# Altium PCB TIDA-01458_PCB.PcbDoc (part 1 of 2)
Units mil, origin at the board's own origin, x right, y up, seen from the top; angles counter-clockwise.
Board outline 4724.41 x 3937.01 mil, 4 copper layers (Top Layer, GND, PWR, Bottom Layer), stack 62.2 mil thick; 188 components, 87 nets, 511 pads, 463 vias.
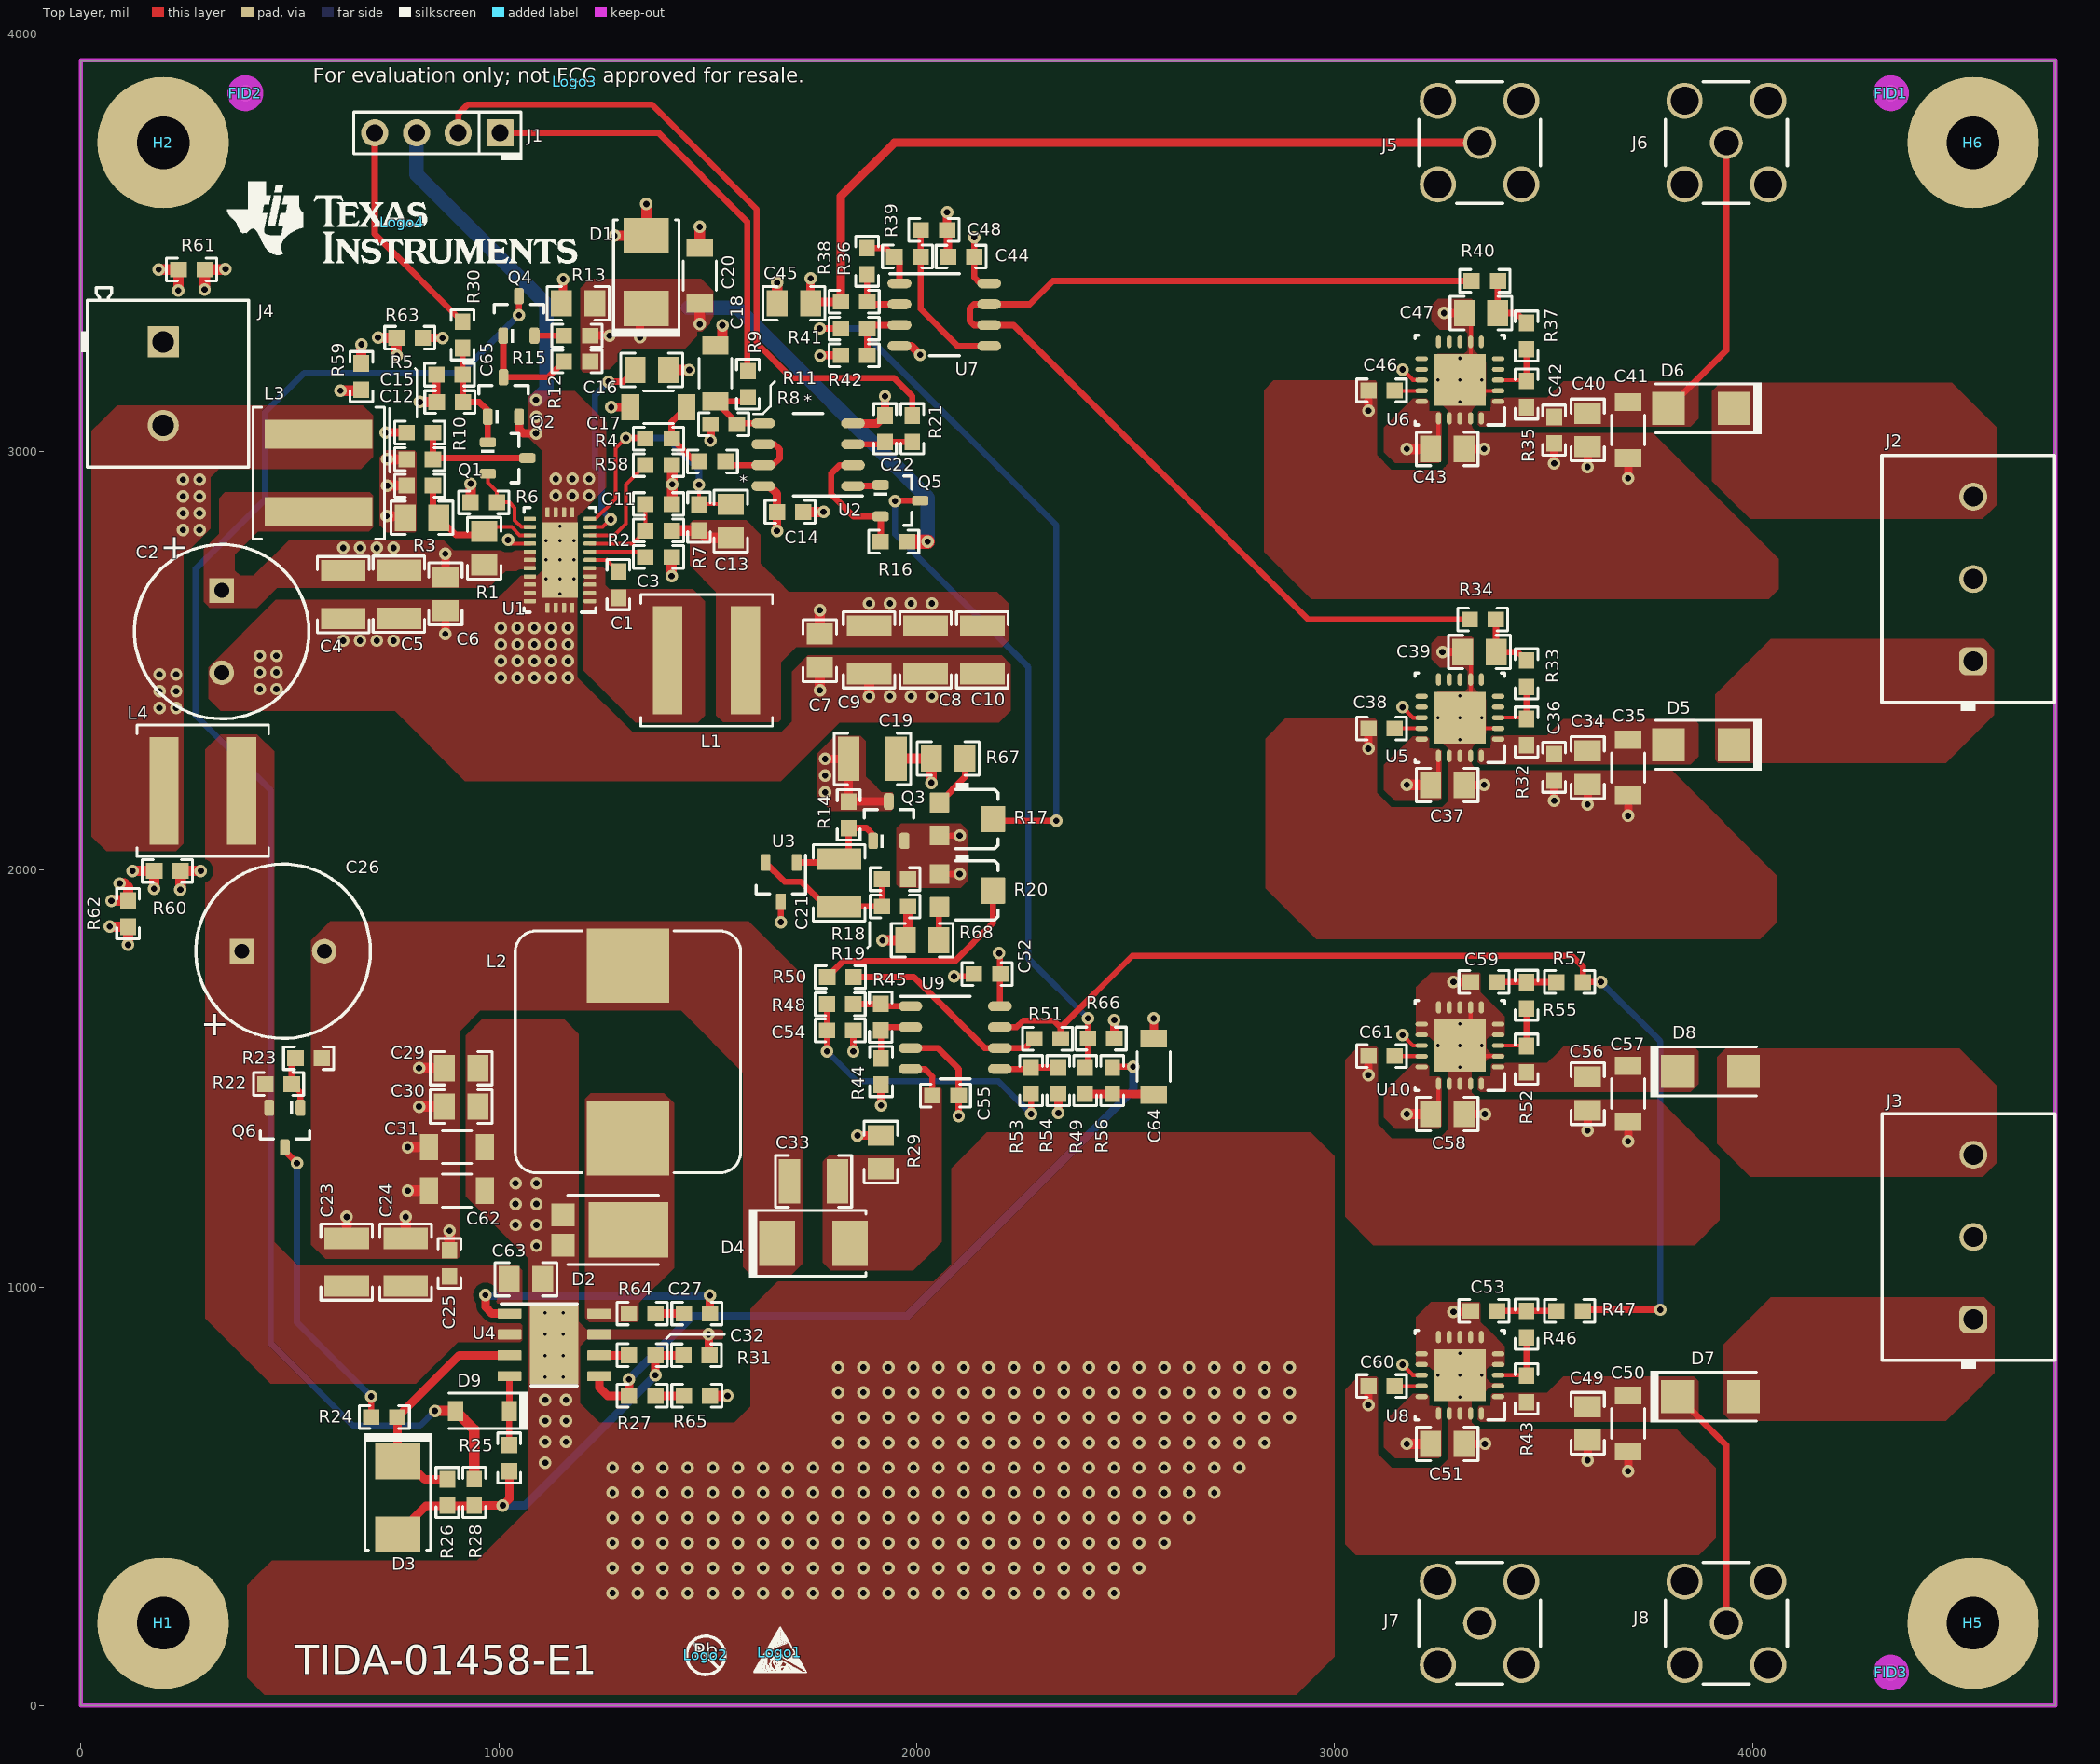
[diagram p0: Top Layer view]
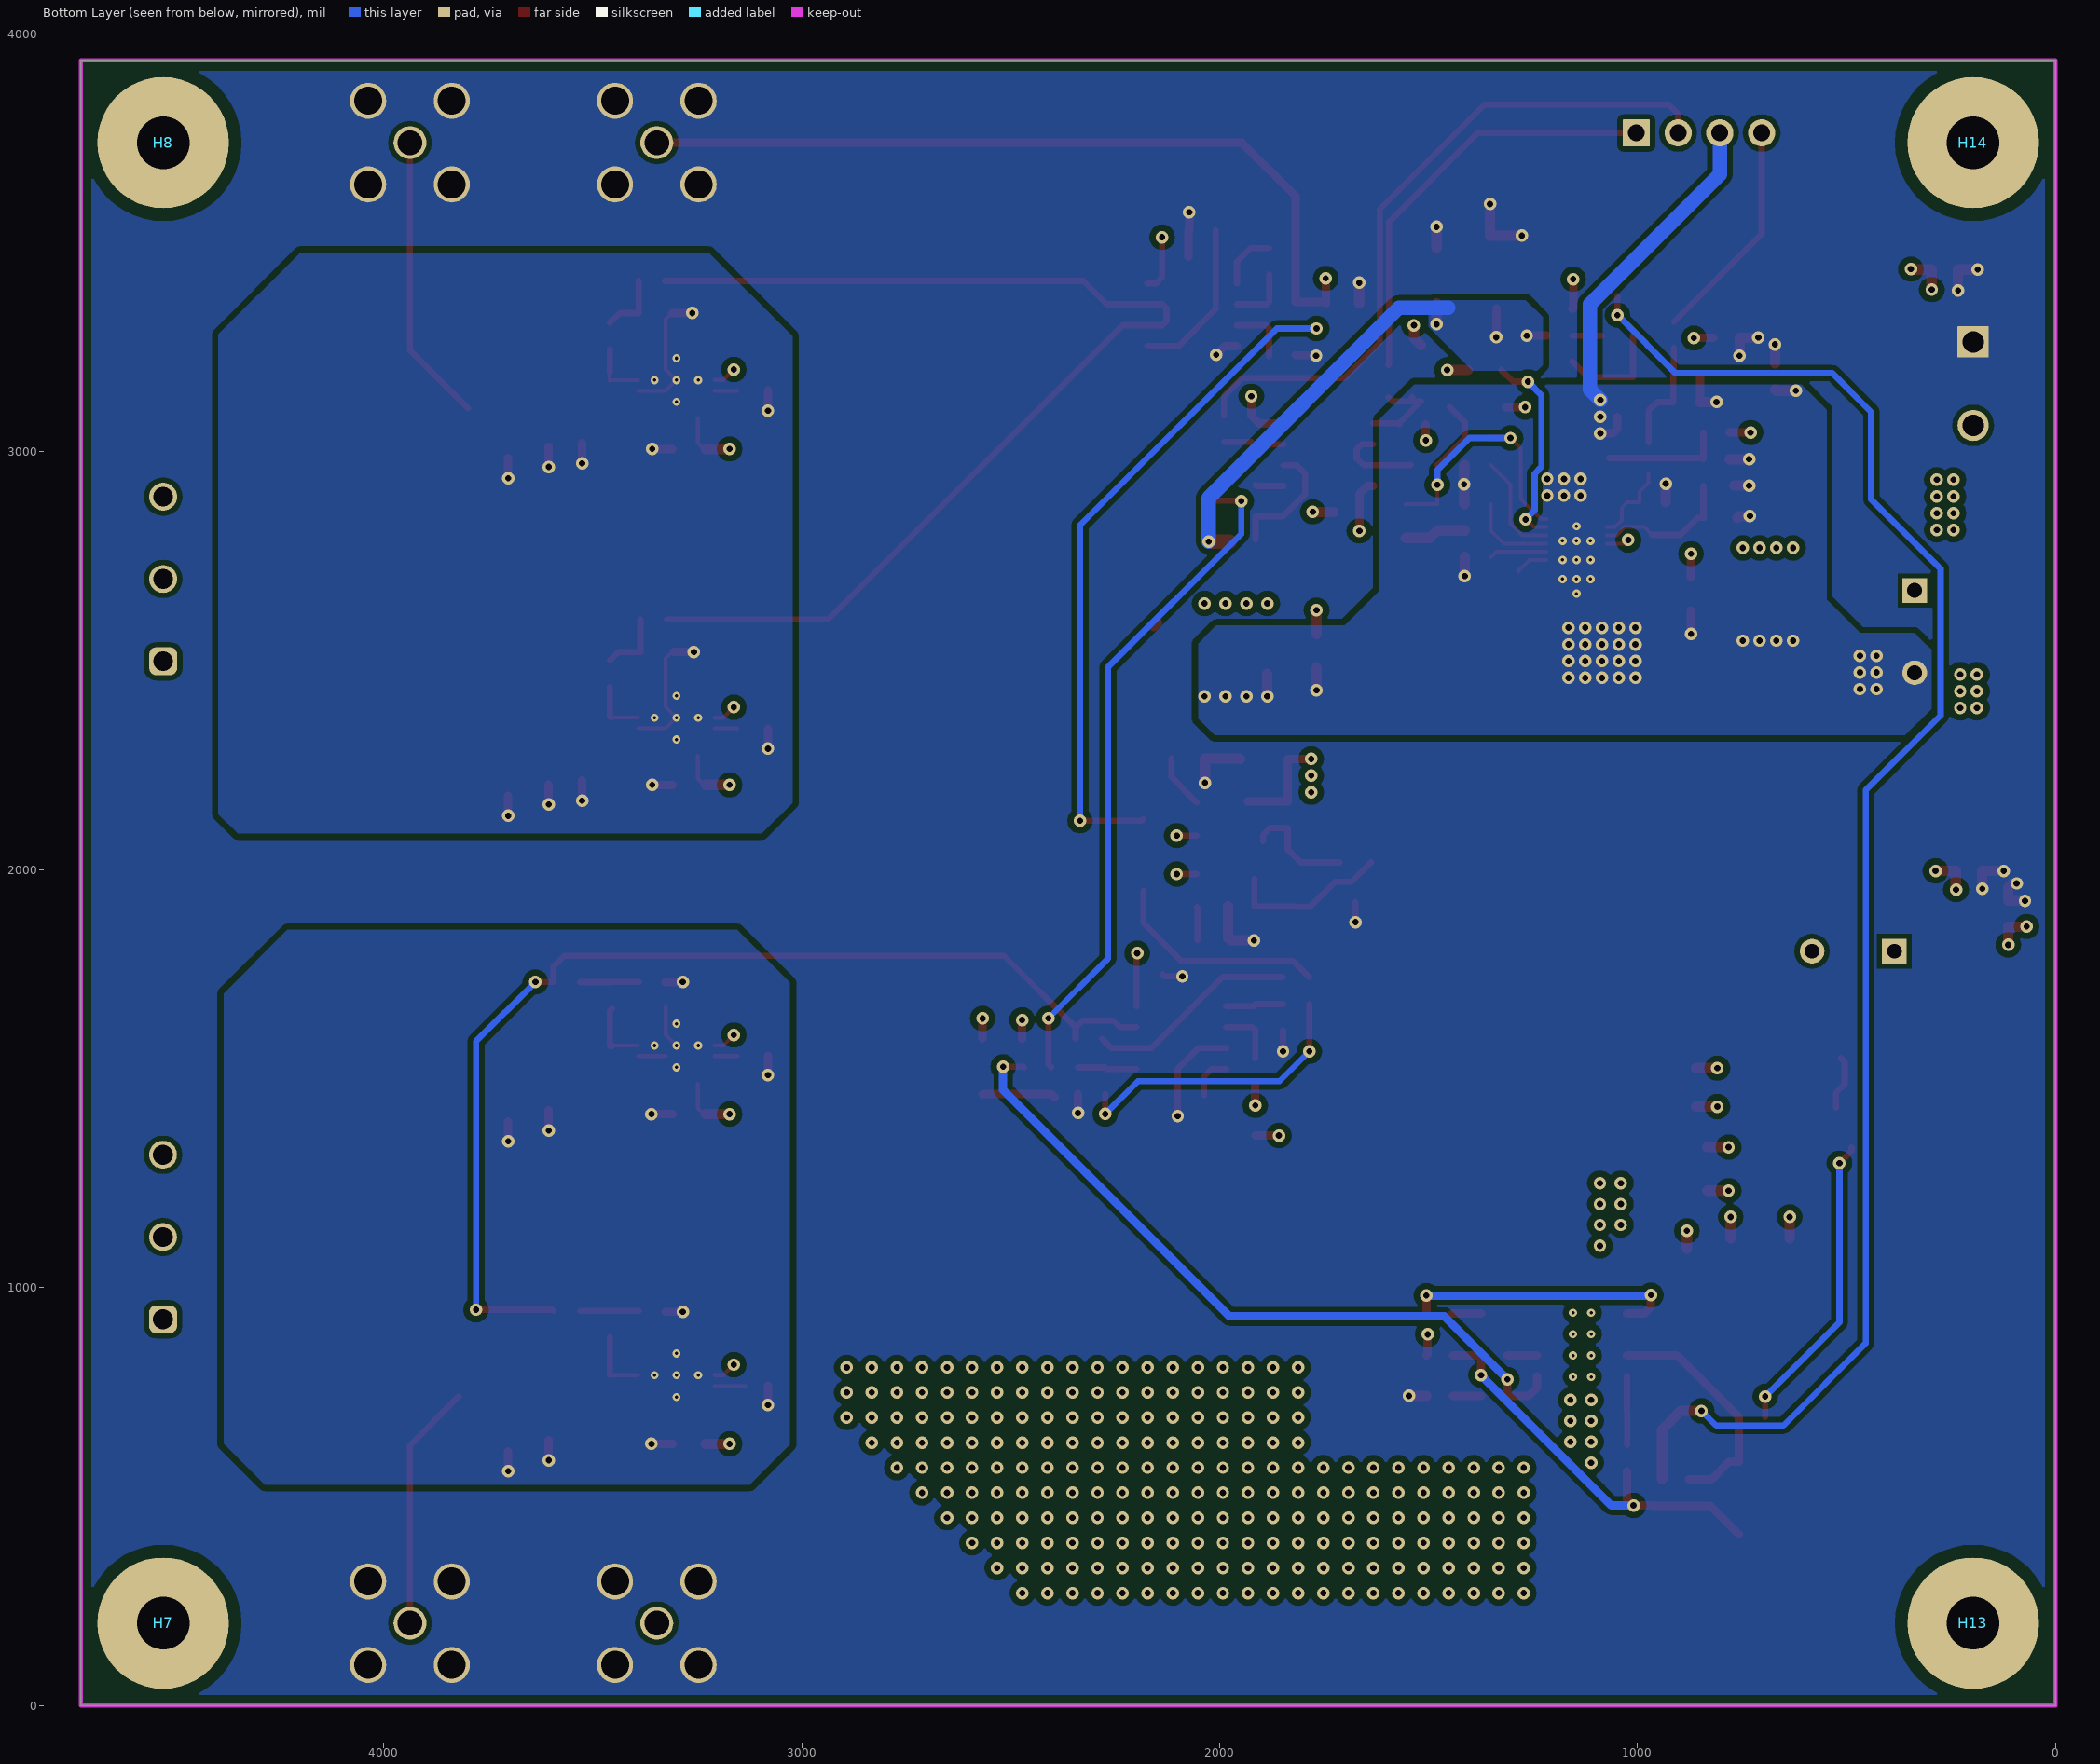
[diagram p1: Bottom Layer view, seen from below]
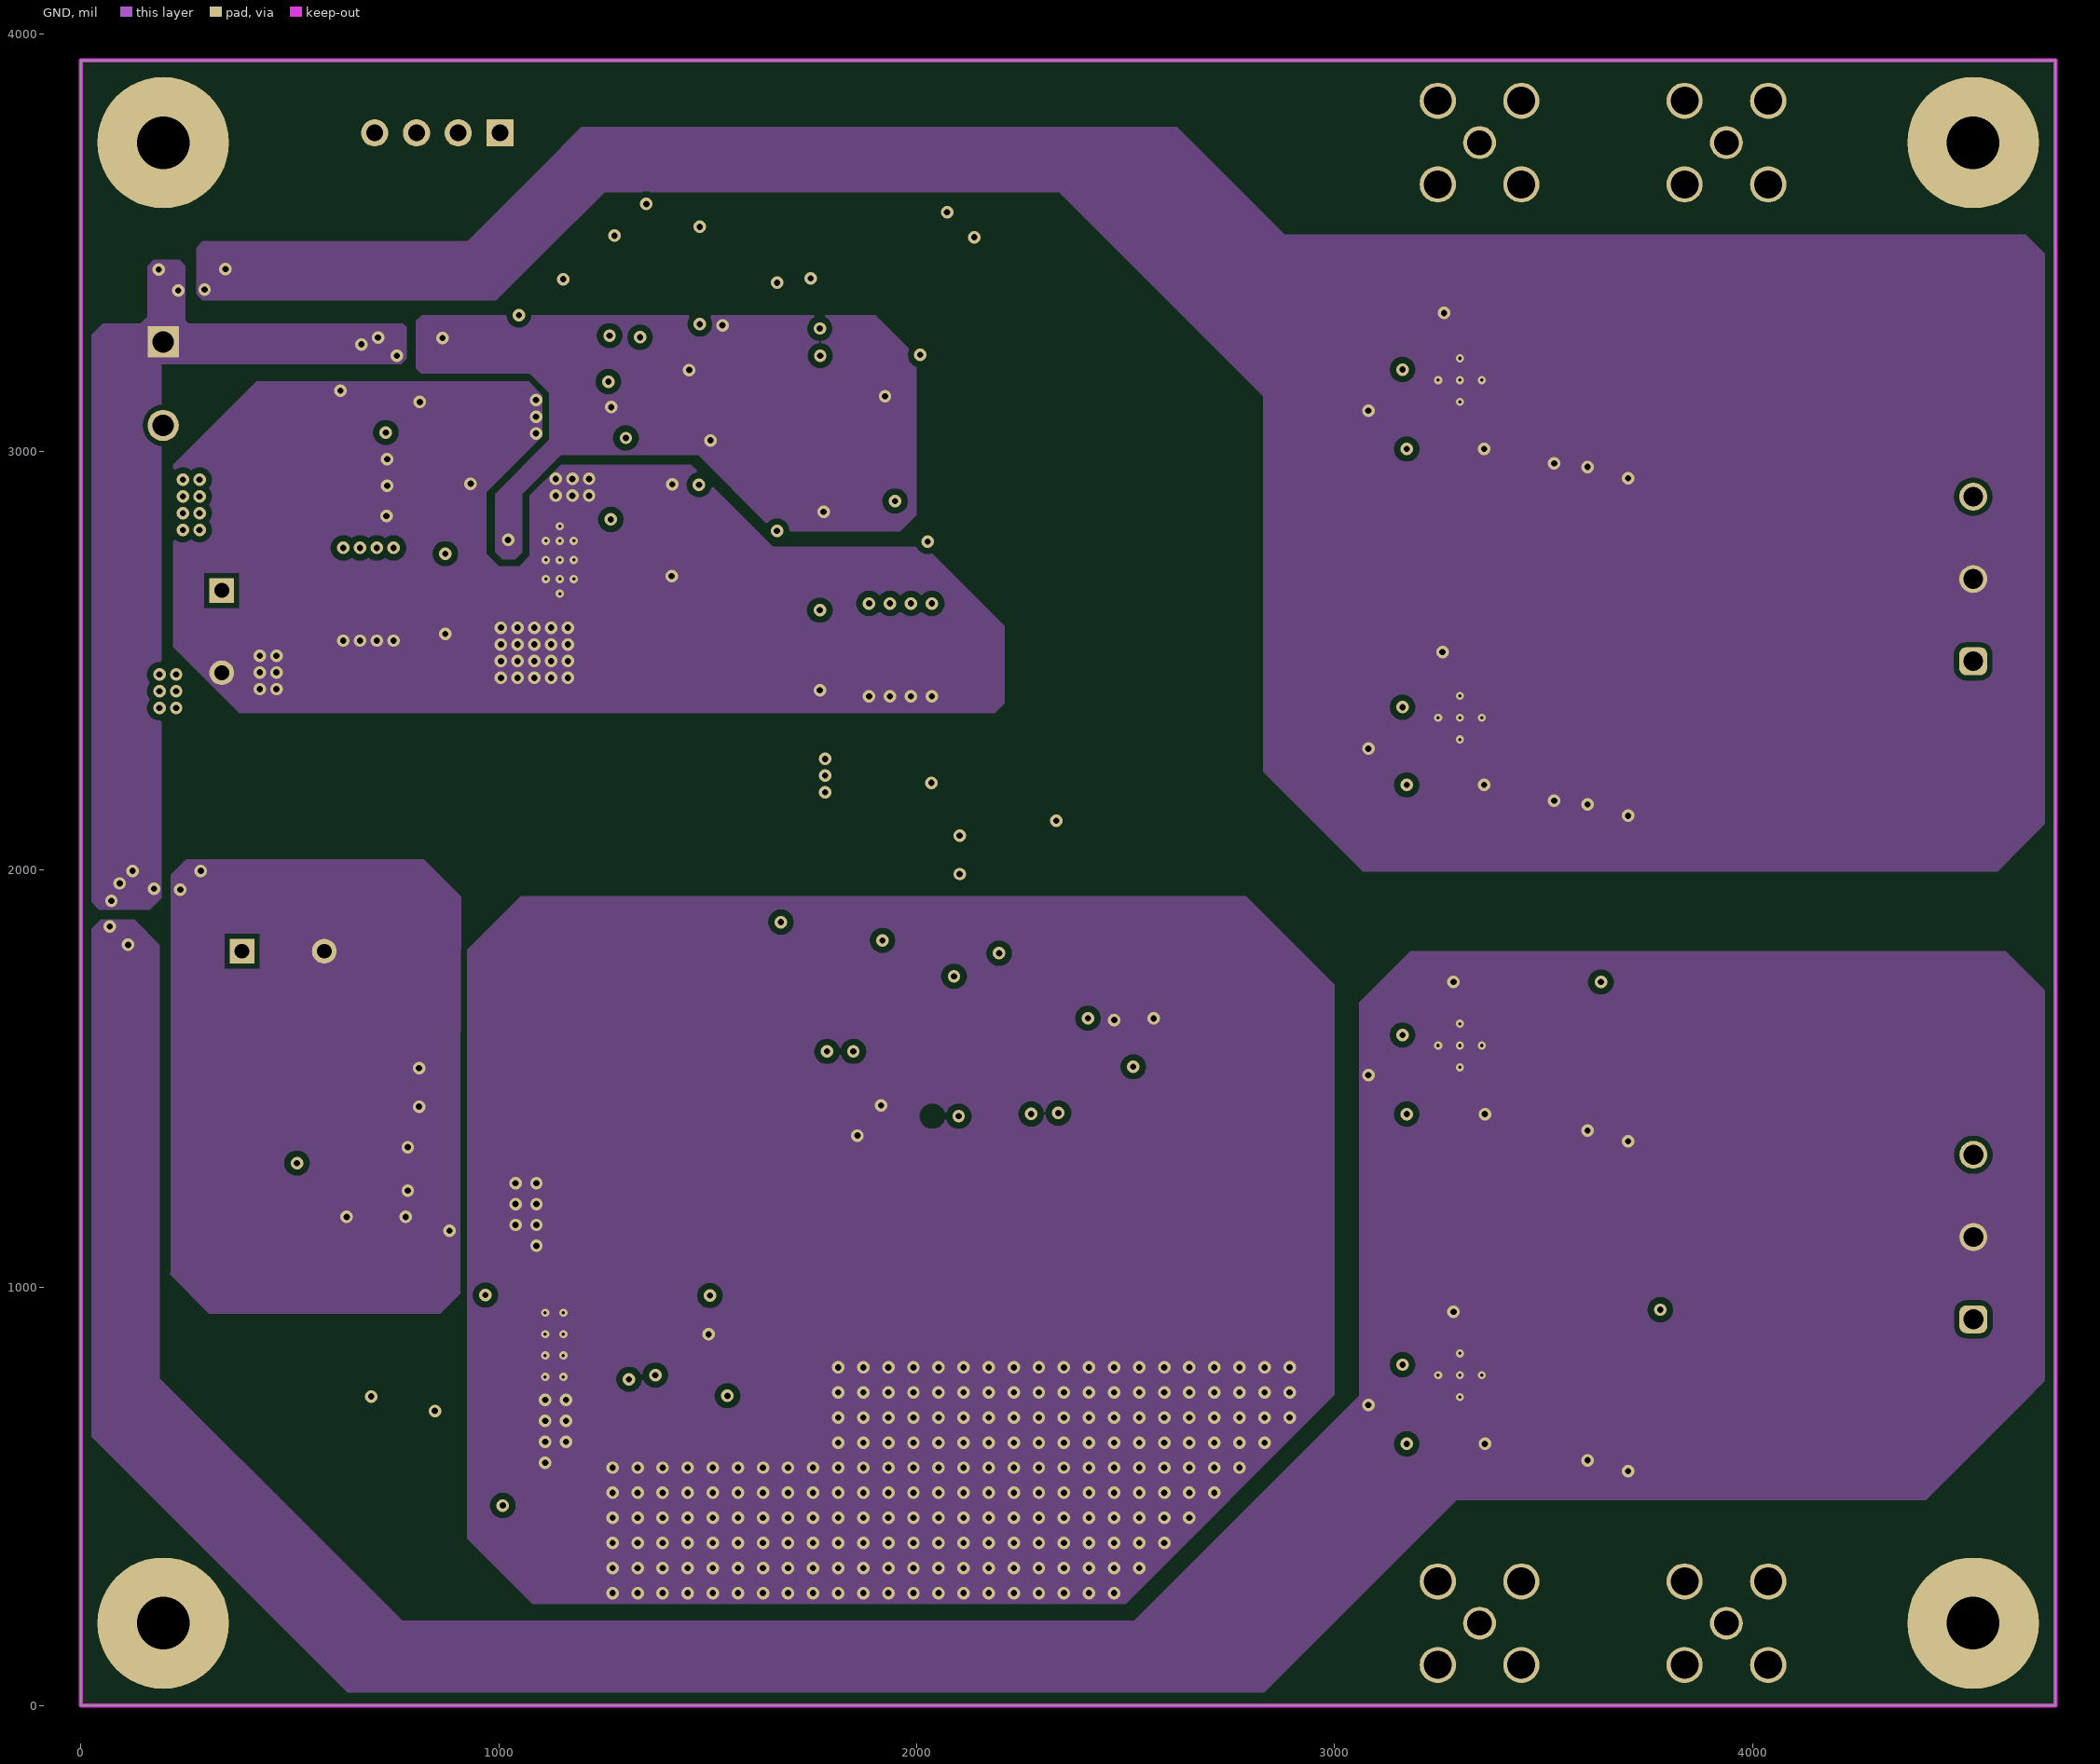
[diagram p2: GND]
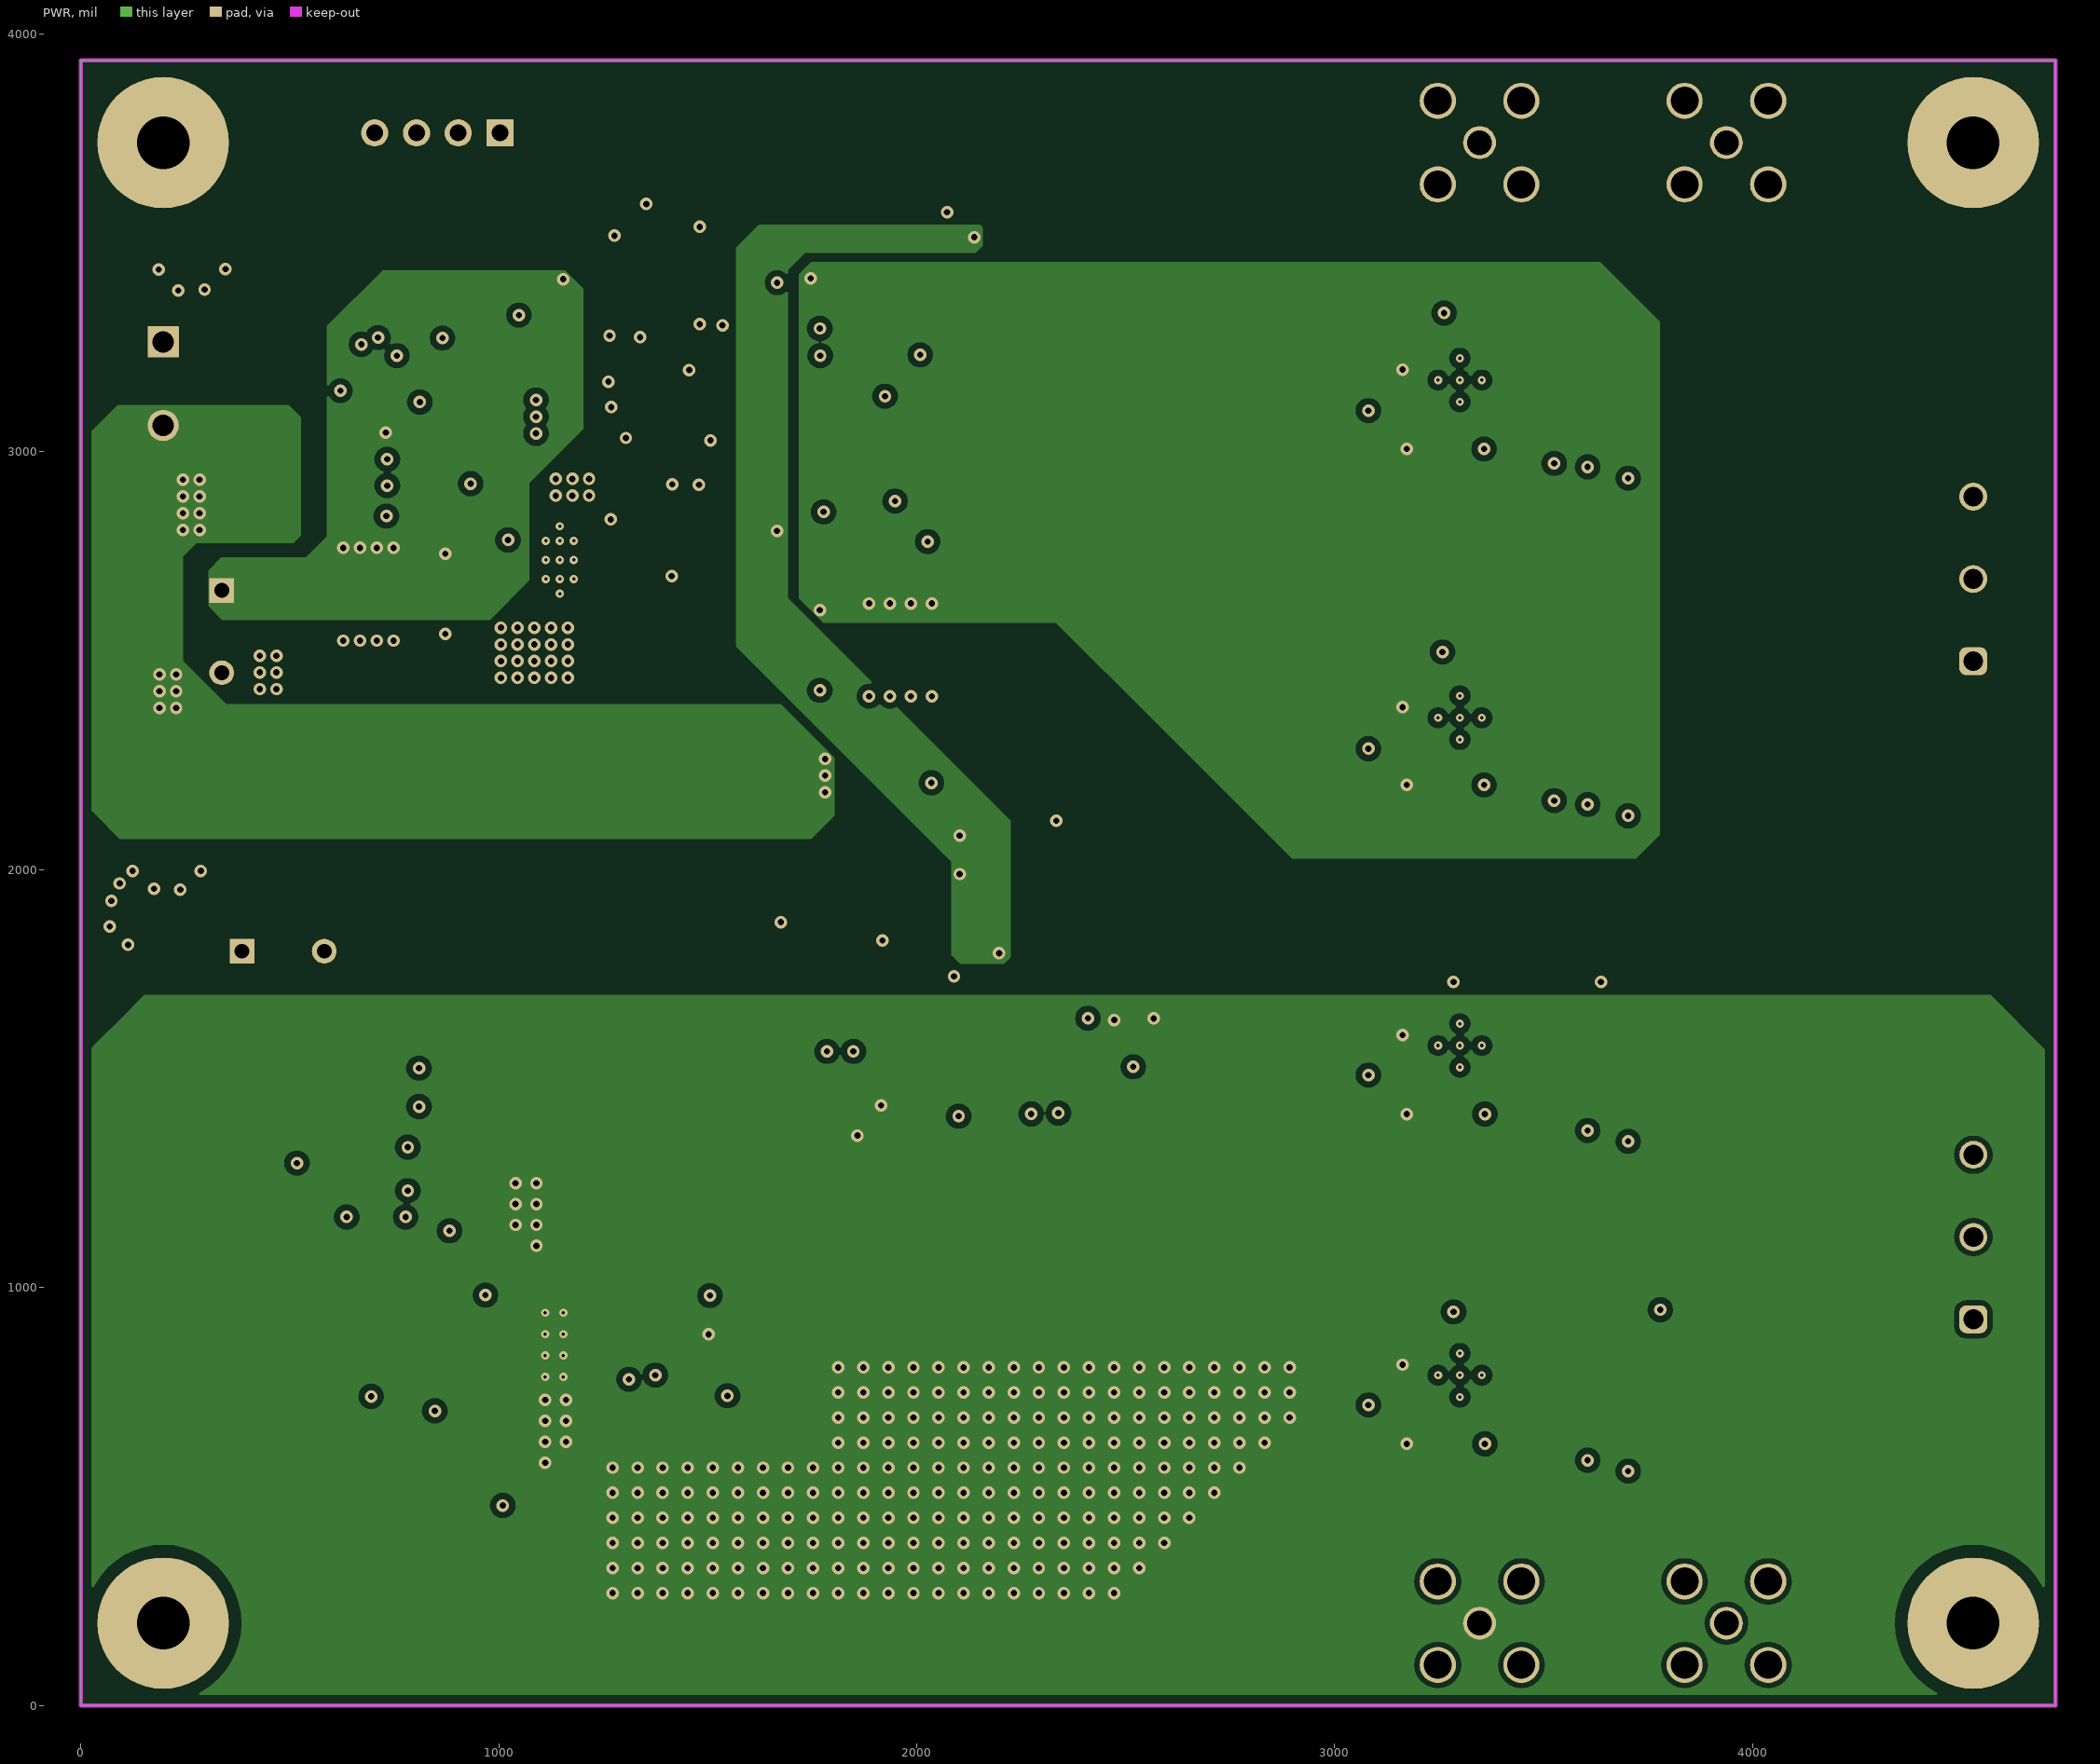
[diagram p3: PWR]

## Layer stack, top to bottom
Top Solder: solder mask 0.4, Solder Resist, Dk 3.5
Top Layer: signal copper 2.8
Dielectric1: core 8, FR-4 High Tg, Dk 4.8
GND: signal copper 2.8
Dielectric 2: prepreg 35, FR-4 High Tg, Dk 4.2
PWR: signal copper 2.8
Dielectric 3: core 8, FR-4 High Tg, Dk 4.2
Bottom Layer: signal copper 2.8
Bottom Solder: solder mask 0.4, Solder Resist, Dk 3.5

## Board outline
0,0 4724.41,0 4724.41,3937.01 0,3937.01

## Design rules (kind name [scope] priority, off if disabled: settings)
AcuteAngle [All] p1: minimum=4.50000000000000E+0001 checktracksonly=FALSE
AssemblyTestPointUsage [All] p1: valid=2
Clearance Clearance_MTG [InPadClass('MTG')] p1: gap=30
Clearance Clearance_Keepouts [IsKeepOut] p2: gap=20
Clearance Clearance_Poly [InPolygon] p3: gap=15 except(12: Track-Poly SMDPad-Poly THPad-Poly)
Clearance [All] p4: gap=7.7
ComponentClearance ComponentClearance_MountingHoles_FiducialMarks [InComponentClass('Mounting Holes') vs InComponentClass('FiducialMark')] p1: gap=10 collisioncheckmode=3 verticalgap=10 showdistances=FALSE
ComponentClearance ComponentClearance_Shunt [InComponentClass('Header') vs InComponentClass('Shunt')] p2: gap=0 collisioncheckmode=3 verticalgap=0 showdistances=FALSE
ComponentClearance ComponentClearance_Logo [InComponentClass('Logo')] p3: gap=20 collisioncheckmode=3 verticalgap=10 showdistances=FALSE
ComponentClearance ComponentClearance_ScrewToNut [(HasFootprint('NY PMS 440 0025 PH')) vs (HasFootprint('Keystone_1902C'))] p4: gap=5 collisioncheckmode=3 verticalgap=10 showdistances=FALSE
ComponentClearance ComponentClearance_MountingHoles [InComponentClass('Mounting Holes')] p5: gap=50 collisioncheckmode=3 verticalgap=100000 showdistances=FALSE
ComponentClearance ComponentClearance_SmallPassives [HasFootprint('0201*') or HasFootprint('0402*') or HasFootprint('0508') or HasFootprint('0603*') or HasFootprint('0612') or HasFootprint('0805*') or HasFootprint('0815*') or HasFootprint('0830*') or HasFootprint('1206*') or HasFootprint('1210*') or HasFootprint('1808*') or HasFootprint('1812*') or HasFootprint('1825*') or HasFootprint('2010*') or HasFootprint('2220*') or HasFootprint('2225*') or HasFootprint('2512*') or HasFootprint('2728*') or HasFootprint('3518*') vs HasFootprint('0201*') or HasFootprint('0402*') or HasFootprint('0508') or HasFootprint('0603*') or HasFootprint('0612') or HasFootprint('0805*') or HasFootprint('0815*') or HasFootprint('0830*') or HasFootprint('1206*') or HasFootprint('1210*') or HasFootprint('1808*') or HasFootprint('1812*') or HasFootprint('1825*') or HasFootprint('2010*') or HasFootprint('2220*') or HasFootprint('2225*') or HasFootprint('2512*') or HasFootprint('2728*') or HasFootprint('3518*')] p6: gap=14.96 collisioncheckmode=3 verticalgap=10 showdistances=FALSE
ComponentClearance ComponentClearance_THtoSMT [IsThruComponent vs IsSMTComponent] p7: gap=5 collisioncheckmode=3 verticalgap=30 showdistances=FALSE
ComponentClearance ComponentClearance_THtoTH [IsThruComponent vs IsThruComponent] p8: gap=10 collisioncheckmode=3 verticalgap=10 showdistances=FALSE
ComponentClearance [All] p9: gap=10 collisioncheckmode=3 verticalgap=10 showdistances=FALSE
DiffPairsRouting [All] p1: maxlimit=100 minlimit=10 mostfreqgap=10 toplayer_minwidth=15 toplayer_maxwidth=15 toplayer_prefwidth=15 midlayer1_minwidth=15 midlayer1_maxwidth=15 midlayer1_prefwidth=15 midlayer2_minwidth=15 midlayer2_maxwidth=15 midlayer2_prefwidth=15 bottomlayer_minwidth=15 bottomlayer_maxwidth=15 bottomlayer_prefwidth=15 maxuncoupledlength=1000
FabricationTestPointUsage TestPointUsage [All] p1: valid=2 allowmultiple=FALSE
FabricationTestpoint Testpoint [All] p1: side=3 testpointundercomponent=TRUE minsize=40 maxsize=100 preferedsize=60 minholesize=0 maxholesize=40 preferedholesize=32 testpointgrid=1 allowsidetop=TRUE allowsidebottom=TRUE usegrid=TRUE gridtolerance=0.01
FanoutControl Fanout_LCC [IsLCC] p1: bgadir=Out bgaviamode=Centered fanoutstyle=Auto fanoutdirection=Alternating viagrid=1 // Fanout_LCC (Default Rule)
FanoutControl Fanout_BGA [IsBGA] p2: bgadir=Out bgaviamode=Centered fanoutstyle=Auto fanoutdirection=Alternating viagrid=1 // Fanout_BGA (Default Rule)
FanoutControl Fanout_Default [All] p4: bgadir=Out bgaviamode=Centered fanoutstyle=Auto fanoutdirection=Alternating viagrid=1 // Fanout_Default (Default Rule)
FanoutControl Fanout_Small [(CompPinCount < 5)] p5: bgadir=Out bgaviamode=Centered fanoutstyle=Auto fanoutdirection=OutThenIn viagrid=1 // Fanout_Small (Default Rule)
Height [All] p1: minheight=0 maxheight=1100 prefheight=500
HoleSize [All] p1: absolutevalues=TRUE maxlimit=251 minlimit=7.87 maxpercent=80.000 minpercent=20.000
MinimumAnnularRing MinimumAnnularRing_ThermalPadVias [IsVia and InAnyComponent] p1: minimumring=5.91
MinimumAnnularRing [All] p2: minimumring=6
MinimumSolderMaskSliver MinimumSolderMaskSliver_Logo [InComponentClass('Logo') vs InComponentClass('Logo')] p1: minsoldermaskwidth=0.7
MinimumSolderMaskSliver [All] p2: minsoldermaskwidth=3.94
PlaneConnect [All] p1: planeconnectstyle=Relief reliefexpansion=10 reliefentries=4 reliefconductorwidth=10 reliefairgap=10
PolygonConnect [All] p1: connectstyle=Direct reliefconductorwidth=10 reliefentries=4 polygonreliefangle="90 Angle" airgapwidth=10
RoutingVias [All] p1: holewidth=12 width=24 viastyle="Through Hole" minholewidth=7.87 minwidth=19.68 maxholewidth=40 maxwidth=65
RoutingVias ThermalPadVias [IsVia and InAnyComponent] p2: holewidth=7.87 width=19.68 viastyle="Through Hole" minholewidth=7.87 minwidth=19.68 maxholewidth=12.99 maxwidth=23.62
SilkToBoardRegionClearance [Not ((IsComment or IsDesignator) And (Hide <> 'False')) and not InRegion(1000,500,4000,800)] p1:
SilkToSilkClearance SilkToSilkClearance_Pb-FreeLogo [(HasFootprint('Pb-Free_Overlay_Medium') OR HasFootprint('Pb-Free_Overlay_Small')) vs (HasFootprint('Pb-Free_Overlay_Medium') OR HasFootprint('Pb-Free_Overlay_Small'))] p1: silktosilkclearance=0
SilkToSilkClearance [All] p2: silktosilkclearance=4
SilkToSolderMaskClearance SilkToComponentPadClearance [IsPad and InAnycomponent] p1: minsilkscreentomaskgap=5 clearancetoexposedcopper=TRUE
SilkToSolderMaskClearance "Silk to Solder Mask Opening" [All] p2: minsilkscreentomaskgap=4 clearancetoexposedcopper=FALSE
SolderMaskExpansion [All] p1: expansion=2.5
Width [All] p1: maxlimit=100 minlimit=6 preferedwidth=10 checkconnectedcopper=TRUE
14 further rules are at their usual default settings.

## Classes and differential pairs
pad class MTG: H1-1 H2-1 H5-1 H6-1
component class AssemblyNote: ZZ1 ZZ2 ZZ3 ZZ4
component class FiducialMark: FID1 FID2 FID3
component class TIDA-01458_Hardware: FID1 FID2 FID3 H1 H2 H5 H6 H7 H8 H13 H14 Logo1 Logo2 Logo3 Logo4 ZZ1 ZZ2 ZZ3 ZZ4
component class "Mounting Holes": H1 H2 H5 H6
component class Header: J1
component class TIDA-01458-Sheet1: C1 C2 C3 C4 C5 C6 C7 C8 C9 C10 C11 C12 C13 C14 C15 C16 C17 C18 C19 C20 C21 C22 C23 C24 C25 C26 C27 C29 C30 C31 C32 C33 C62 C63 C64 C65 D1 D2 D3 D4 D9 J1 J4 L1 L2 L3 L4 Q1 Q2 Q3 Q4 Q5 Q6 R1 R2 R3 R4 R5 R6 R7 R8 R9 R10 R11 R12 R13 R14 R15 R16 R17 R18 R19 R20 R21 R22 R23 R24 R25 R26 R27 R28 R29 R30 R31 R49 R56 R58 R64 R65 R66 R67 R68 U1 U2 U3 U4
component class TIDA-01458_Sheet2: C34 C35 C36 c37 c38 C39 C40 C41 C42 C43 C44 C45 C46 C47 C48 C49 C50 C51 C52 C53 C54 C55 C56 C57 C58 C59 C60 C61 D5 D6 D7 D8 J2 J3 J5 J6 J7 J8 R32 R33 R34 R35 R36 R37 R38 R39 R40 R41 R42 R43 R44 R45 R46 R47 R48 R50 R51 R52 R53 R54 R55 R57 R59 R60 R61 R62 R63 U5 U6 U7 U8 U9 U10
component class Logo: Logo4

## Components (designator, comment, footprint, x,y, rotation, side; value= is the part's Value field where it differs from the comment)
C1 "GRM188R61E474KA12D" 0603 1286,2682.25 r90 top
C2 "35ZL470MEFC10X20" ZL_1000x2000 337,2569.83 r270 top
C3 "C1608X5R1V225K080AC" 0603 1382,2748.25 r180 top
C4 "GRM32ER71H106KA12L" 1210_270 628,2658.25 r90 top
C5 "GRM32ER71H106KA12L" 1210_270 761,2659.25 r90 top
C6 "GRM21BR71H474KA88L" 0805_HV 872,2660.25 r90 top
C7 "GRM21BR71H474KA88L" 0805_HV 1768,2524.25 r90 top
C8 "GRM32ER71E226KE15L" 1210_270 2021,2526.25 r270 top
C9 "GRM32ER71E226KE15L" 1210_270 1886,2526.25 r270 top
C10 "GRM32ER71E226KE15L" 1210_270 2157,2526.25 r270 top
C11 "C1608X5R1H105K080AB" 0603 1382,2875.05 r180 top
C12 "C1608X7R1H104K080AA" 0603 811,2919.25 r180 top
C13 "08055A4R7CAT2A" 0805_HV 1555,2834.25 r270 top
C14 "C1608X7R1H104K080AA" 0603 1697,2856.25 r0 top
C15 "C1608X7R1H104K080AA" 0603 811,2982.25 r180 top
C16 "08055C223KAT2A" 0805_HV 1366,3196 r180 top
C17 "C3216X5R1H106K160AB" 1206_180 1382,3107 r180 top
C18 "C3216X5R1H106K160AB" 1206_180 1518,3188 r90 top
C19 "GRM32ER71H106KA12L" 1210_270 1894,2265.25 r0 top
C20 "C3216X5R1H106K160AB" 1206_180 1481,3422 r90 top
C21 "GRM32ER71H106KA12L" 1210_270 1814,1968.25 r270 top
C22 "C1608X7R1H104K080AA" 0603 1924,3055.25 r90 top
C23 "GRM32ER71H475KA88L" 1210_270 636,1061 r90 top
C24 "GRM32ER71H475KA88L" 1210_270 777,1061 r90 top
C25 "C1608X7R1H104K080AA" 0603 882,1058 r90 top
C26 "35ZL470MEFC10X20" ZL_1000x2000 484,1805 r0 top
C27 "C1608X7R1H104K080AA" 0603 1474,938 r0 top
C29 "GRM21BR71E105KA99L" 0805_HV 910,1525 r0 top
C30 "GRM21BR71E105KA99L" 0805_HV 910,1433 r0 top
C31 "C3216X5R1E476M160AC" 1206_190 900,1336 r0 top
C32 "GRM188R71E273KA01D" 0603 1343,838 r0 top
C33 "GRM32ER71E226KE15L" 1210_270 1753,1254 r180 top
C34 "C2012X5R1V106K085AC" 0805_HV 3605,2244.25 r90 top
C35 "C3216X5R1E476M160AC" 1206_190 3702,2244.25 r270 top
C36 "C1608X7R1H104K080AA" 0603 3525,2245.25 r270 top
C37 "C2012X5R1V106K085AC" 0805_HV 3269,2203 r180 top
C38 "C1608X5R1H105K080AB" 0603 3112,2338 r0 top
C39 "C2012X5R1V106K085AC" 0805_HV 3346,2521 r0 top
C40 "C2012X5R1V106K085AC" 0805_HV 3605,3052.25 r90 top
C41 "C3216X5R1E476M160AC" 1206_190 3702,3052.25 r270 top
C42 "C1608X7R1H104K080AA" 0603 3525,3052 r270 top
C43 "C2012X5R1V106K085AC" 0805_HV 3269,3007 r180 top
C44 "C1608X7R1H104K080AA" 0603 2106,3467.25 r180 top
C45 "C2012X5R1V106K085AC" 0805_HV 1705.85,3355.3 r0 top
C46 "C1608X5R1H105K080AB" 0603 3112,3147 r0 top
C47 "C2012X5R1V106K085AC" 0805_HV 3350,3332.25 r0 top
C48 "C1608X5R1H105K080AB" 0603 2041,3531.25 r180 top
C49 "C2012X5R1V106K085AC" 0805_HV 3605,675 r90 top
C50 "C3216X5R1E476M160AC" 1206_190 3702,675 r270 top
C51 "C2012X5R1V106K085AC" 0805_HV 3269,626 r180 top
C52 "C1608X7R1H104K080AA" 0603 2168.17,1750.23 r180 top
C53 "C1608X5R1H105K080AB" 0603 3357,944 r0 top
C54 "C1608X7R1H104K080AA" 0603 1816.72,1615.25 r180 top
C55 "C1608X7R1H104K080AA" 0603 2068.72,1459.25 r0 top
C56 "C2012X5R1V106K085AC" 0805_HV 3605,1464.25 r90 top
C57 "C3216X5R1E476M160AC" 1206_190 3702,1464.25 r270 top
C58 "C2012X5R1V106K085AC" 0805_HV 3269,1415.25 r180 top
C59 "C1608X5R1H105K080AB" 0603 3357,1731.25 r0 top
C60 "C1608X5R1H105K080AB" 0603 3112,764.25 r0 top
C61 "C1608X5R1H105K080AB" 0603 3112,1554.25 r0 top
C62 "C3216X5R1E476M160AC" 1206_190 900,1232 r0 top
C63 "GRM21BR71E105KA99L" 0805_HV 1065,1020 r0 top
C64 "C3216X5R1H106K160AB" 1206_180 2567,1529 r90 top
C65 "06035A220JAT2A" 0603 882,3185 r180 top
D1 "1SMB5913BT3G" SMB 1353,3430.25 r90 top
D2 "PDS760-13" PowerDI5 1232,1138 r0 top
D3 "1SMB5913BT3G" SMB 758,497 r270 top
D4 "1SMB5913BT3G" SMB 1753,1106 r0 top
D5 "B260A-13-F" SMA 3877.05,2299.25 r180 top
D6 "B260A-13-F" SMA 3877.05,3104.25 r180 top
D7 "B260A-13-F" SMA 3899,739.25 r0 top
D8 "B260A-13-F" SMA 3899,1517.25 r0 top
D9 "1N4148W-TP" SOD-123 961,705 r180 top
FID1 "Fiducial" Fiducial10-20 4330.71,3858.27 r90 top
FID2 "Fiducial" Fiducial10-20 393.7,3858.27 r0 top
FID3 "Fiducial" Fiducial10-20 4330.71,78.74 r90 top
H1 "NY PMS 440 0025 PH" "NY PMS 440 0025 PH" 196.85,196.85 r0 top
H2 "NY PMS 440 0025 PH" "NY PMS 440 0025 PH" 196.85,3740.16 r0 top
H5 "NY PMS 440 0025 PH" "NY PMS 440 0025 PH" 4527.56,196.85 r0 top
H6 "NY PMS 440 0025 PH" "NY PMS 440 0025 PH" 4527.56,3740.16 r0 top
H7 "1902C" Keystone_1902C 4527.56,196.85 r180 bottom locked
H8 "1902C" Keystone_1902C 4527.56,3740.16 r180 bottom
H13 "1902C" Keystone_1902C 196.85,196.85 r180 bottom locked
H14 "1902C" Keystone_1902C 196.85,3740.16 r180 bottom
J1 "TSW-104-07-G-S" TSW-104-07-G-S 853,3763.25 r180 top
J2 "1792876" Phoenix_1792876 4527.56,2695.85 r90 top
J3 "1792876" Phoenix_1792876 4528,1121 r90 top
J4 "1715721" PhoenixContact_1715721 197,3163.25 r270 top
J5 "901-144-8RFX" Amphenol_901-144-8RFX 3346.46,3740.16 r0 top
J6 "901-144-8RFX" Amphenol_901-144-8RFX 3937.01,3740.16 r0 top
J7 "901-144-8RFX" Amphenol_901-144-8RFX 3346.46,196.85 r0 top
J8 "901-144-8RFX" Amphenol_901-144-8RFX 3937.01,196.85 r0 top
L1 "XAL7030-103MEB" XAL7030 1497,2501.25 r0 top
L2 "7443551331" WE-HCA1 1309,1564 r90 top locked
L3 "XAL7030-222MEB" XAL7030 569,2949.25 r270 top
L4 "XAL7030-222MEB" XAL7030 292,2189 r0 top
Logo1 "ESD Susceptible" ESD_Overlay_Small 1672,127 r0 top
Logo2 "Pb-Free Symbol" Pb-Free_Overlay_Small 1495,120 r0 top
Logo3 "FCC disclaimer" FCC_disclaimer 1182,3885.25 r0 top
Logo4 "Texas Instruments" TI_Stacked_Overlay_Small 769,3549.25 r0 top
Q1 "BC847CLT1G" SOT-23 1021,2985.25 r0 top
Q2 "BSS123" SOT-23 1011,3131.25 r90 top
Q3 "BC847CLT1G" SOT-23 1933,2116.25 r90 top
Q4 "BC857C-7-F" SOT-23 1048,3325.25 r90 top
Q5 "BC857C-7-F" SOT-23 1961,2883.25 r0 top
Q6 "BC857C-7-F" SOT-23 488,1383 r270 top
R1 "CRCW0805240KJNEA" 0805_HV 965,2769.25 r270 top
R2 "CRCW06030000Z0EA" 0603 1382,2811.65 r180 top
R3 "CRCW080547K0JNEA" 0805_HV 816,2842.25 r0 top
R4 "CRCW060368K0JNEA" 0603 1382,3031.85 r180 top
R5 "CRCW0603470RJNEA" 0603 811,3046.25 r180 top
R6 "CRCW0603100RFKEA" 0603 964,2879.25 r0 top
R7 "CRCW06031M00FKEA" 0603 1479,2843.25 r90 top
R8 "RC0603FR-074K7L" 0603 1511,2977.25 r180 top
R9 "CRCW060320K0JNEA" 0603 1596,3162 r270 top
R10 "RC0603FR-074K7L" 0603 883,3119.25 r0 top
R11 "CRCW060310K0FKEA" 0603 1538,3066 r0 top
R12 "CRCW06031K00FKEA" 0603 1187,3216.25 r180 top
R13 "CRCW08052K00JNEA" 0805_HV 1190,3355.25 r180 top
R14 "RC0603FR-074K7L" 0603 1837,2131.25 r90 top
R15 "CRCW06033K30JNEA" 0603 1187,3278.25 r0 top
R16 "CRCW06033K30JNEA" 0603 1945,2785.25 r0 top
R17 "TC33X-2-103E" Bourns_TC33X-2 2125,2121.25 r0 top
R18 "CRCW0603180KJNEA" 0603 1948,1977.25 r0 top
R19 "CRCW060333K0JNEA" 0603 1948,1912.25 r180 top
R20 "TC33X-2-103E" Bourns_TC33X-2 2125,1950.25 r0 top
R21 "CRCW06032K20JNEA" 0603 1989,3055.25 r90 top
R22 "CRCW06033K60JNEA" 0603 473,1487 r180 top
R23 "CRCW0603100KFKEA" 0603 545,1549 r180 top
R24 "CRCW060322K0JNEA" 0603 726,690 r0 top
R25 "CRCW060359K0FKEA" 0603 1025,592 r90 top
R26 "CRCW0603100KFKEA" 0603 877,509.5 r270 top
R27 "CRCW0603442KFKEA" 0603 1343,741 r0 top
R28 "CRCW06033K30JNEA" 0603 941,510 r90 top
R29 "CRCW0805470RJNEA" 0805_HV 1914,1324 r90 top
R30 "CRCW0603220RJNEA" 0603 913,3280 r270 top
R31 "CRCW06030000Z0EA" 0603 1473,838 r180 top
R32 "CRCW0603100KFKEA" 0603 3459,2329.5 r90 top
R33 "CRCW060310K0FKEA" 0603 3459,2469.04 r90 top
R34 "CRCW0603330RJNEA" 0603 3354,2599 r0 top
R35 "CRCW0603100KFKEA" 0603 3459,3138.5 r90 top
R36 "CRCW060310K0FKEA" 0603 1881,3456.25 r270 top
R37 "CRCW060310K0FKEA" 0603 3459,3277.04 r90 top
R38 "CRCW0603100KFKEA" 0603 1850,3359.25 r180 top
R39 "CRCW060310K0FKEA" 0603 1977.85,3467.3 r180 top
R40 "CRCW0603330RJNEA" 0603 3359,3409 r0 top
R41 "CRCW0603100KFKEA" 0603 1850,3295.25 r180 top
R42 "CRCW060310K0FKEA" 0603 1850.04,3231.19 r0 top
R43 "CRCW06031M20JNEA" 0603 3458.93,757.5 r270 top
R44 "CRCW0603100KFKEA" 0603 1914.72,1517.25 r270 top
R45 "CRCW0603100KFKEA" 0603 1913.72,1647.25 r270 top
R46 "CRCW0603100KFKEA" 0603 3459,912.5 r90 top
R47 "CRCW060310K0FKEA" 0603 3562,944 r0 top
R48 "CRCW060310K0FKEA" 0603 1816.72,1678.25 r180 top
R49 "CRCW06031K00FKEA" 0603 2402.72,1495.25 r270 top
R50 "CRCW0603120KJNEA" 0603 1817.17,1743.23 r180 top
R51 "CRCW060310K0FKEA" 0603 2312.72,1595.25 r180 top
R52 "CRCW06031M20JNEA" 0603 3458.93,1546.5 r270 top
R53 "CRCW0603120KJNEA" 0603 2273.72,1495.25 r90 top
R54 "CRCW060310K0FKEA" 0603 2338.72,1495.25 r90 top
R55 "CRCW0603100KFKEA" 0603 3459,1699.5 r90 top
R56 "CRCW060322K0JNEA" 0603 2467.72,1495.25 r90 top
R57 "CRCW060310K0FKEA" 0603 3562,1731.18 r0 top
R58 "CRCW060393K1FKEA" 0603 1382,2968.39 r0 top
R59 "CRCW06030000Z0EA" 0603 671,3180.25 r90 top
R60 "CRCW06030000Z0EA" 0603 207,1997.25 r180 top
R61 "CRCW06030000Z0EA" 0603 265,3436.25 r180 top
R62 "CRCW06030000Z0EA" 0603 113,1895.25 r90 top
R63 "CRCW06030000Z0EA" 0603 787,3273.25 r180 top
R64 "CRCW060310R0JNEA" 0603 1343,938 r0 top
R65 "CRCW0603100RFKEA" 0603 1474,741 r0 top
R66 "CRCW06031K00FKEA" 0603 2441,1596 r180 top
R67 "CRCW080547K0JNEA" 0805_HV 2075,2266 r180 top
R68 "CRCW080547K0JNEA" 0805_HV 2013,1831 r0 top
U1 "LM73605RNPR" RNP0030A 1146,2741.25 r180 top
U2 "TLV2171IDR" D0008A_N 1740,2993.25 r180 top
U3 "TL431ACDBZR" DBZ0003A_N 1675,1970.25 r270 top
U4 "LMR14050SDDAR" DDA0008E_N 1132.72,863 r0 top
U5 "TPS7A4701RGWR" RGW0020A 3299.5,2363.79 r180 top
U6 "TPS7A4701RGWR" RGW0020A 3299.5,3171.79 r180 top
U7 "TLV2171IDR" D0008A_N 2065.85,3328.3 r0 top
U8 "TPS7A3301RGWR" RGW0020A 3299.5,790.25 r180 top
U9 "TLV2171IDR" D0008A_N 2091.72,1598.25 r0 top
U10 "TPS7A3301RGWR" RGW0020A 3299.5,1579.25 r180 top
ZZ1 "These assemblies must comply with workmanship standards IPC-A-610 Class 2, unless otherwise specified." AssemblyNote -162,5698.25 r0 top
ZZ2 "These assemblies must be clean and free from flux and all contaminants. Use of no clean flux is not acceptable." AssemblyNote -162,5587.25 r0 top
ZZ3 "These assemblies are ESD sensitive, ESD precautions shall be observed." AssemblyNote -162,5482.25 r0 top
ZZ4 "This Assembly Note is for PCB labels only" AssemblyNoteLabel -162,5380.25 r0 top

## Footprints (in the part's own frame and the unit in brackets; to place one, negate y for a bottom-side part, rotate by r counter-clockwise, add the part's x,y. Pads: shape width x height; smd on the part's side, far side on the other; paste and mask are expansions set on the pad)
0603 [mm] "0603 from SM-752 data"
  rect 1x0.95 smd: 1(-0.8,0) 2(0.8,0)
  silkscreen extent -1.52,-0.69 1.52,0.69, body extent -0.87,-0.47 0.87,0.47, height 1
0805_HV [mil] "0805 with 30mil clearance between pads"
  rect 50x63 smd: 1(-40,0) 2(40,0)
  silkscreen extent -74,-40 74,40, body extent -43,-29 43,29, height 57
1206_180 [mm] "1206_180"
  rect 1.1x1.6 smd: 1(-1.7,0) 2(1.7,0)
  silkscreen extent -0.9,-1 0.9,1, body extent -1.75,-0.95 1.75,0.95, height 1.8
1206_190 [mm] "1206_190"
  rect 1.1x1.6 smd: 1(-1.7,0) 2(1.7,0)
  silkscreen extent -0.9,-1 0.9,1, body extent -1.75,-0.95 1.75,0.95, height 1.9
1210_270 [mm] "1210"
  rect 1.3x2.7 smd: 1(-1.45,0) 2(1.45,0)
  silkscreen extent -2.32,-1.57 2.32,1.57, body extent -1.7,-1.35 1.7,1.35, height 2.7
Amphenol_901-144-8RFX [mm] "SMA Straight Jack, TH"
  round 2 hole 1.5: 1(0,0)
  round 2.2 hole 1.7: 2(-2.54,2.54) 3(-2.54,-2.54) 4(2.54,-2.54) 5(2.54,2.54)
  silkscreen extent -3.7,-3.7 3.7,3.7, body extent -3.7,-3.7 3.7,3.7, height 9.93
AssemblyNote [mil] "Assembly Note"
AssemblyNoteLabel [mil] "Assembly Note for PCB Labels"
Bourns_TC33X-2 [mm] "SMD, 3-Leads, Body 3.8x3.6mm"
  rrect8% 1.2x1.2 smd: 1(-1.8,1) 3(-1.8,-1)
  rrect7% 1.5x1.6 smd: 2(1.45,0)
  silkscreen extent -0.8,-1.8 1.75,2.2, body extent -1.96,-1.8 2,1.8, height 1.13
D0008A_N [mm] "SOIC, 8-Leads, Body 4.9x3.9mm, Pitch 1.27mm, IPC Medium Density"
  oval 1.45x0.6 smd: 1(-2.725,1.905) 2(-2.725,0.635) 3(-2.725,-0.635) 4(-2.725,-1.905) 5(2.725,-1.905) 6(2.725,-0.635) 7(2.725,0.635) 8(2.725,1.905)
  silkscreen extent -3.3,-2.5 0.9,2.5, body extent -3,-2.45 3,2.45, height 1.63
DBZ0003A_N [mm] "SOT23, 3-Leads, Body 2.9x1.3mm, Pitch 0.95mm, Lead Span 2.4mm, IPC Medium Density"
  rrect17% 1x0.6 smd: 1(-1.2,0.95) 2(-1.2,-0.95) 3(1.2,0)
  silkscreen extent -1.65,-1.5 0.7,1.5, body extent -1.26,-1.46 1.26,1.46, height 0.98
DDA0008E_N [mm]
  rrect17% 1.45x0.6 smd: 1(-2.725,1.905) 2(-2.725,0.635) 3(-2.725,-0.635) 4(-2.725,-1.905) 5(2.725,-1.905) 6(2.725,-0.635) 7(2.725,0.635) 8(2.725,1.905)
  rrect7% 2.95x4.9 smd paste-1.5: 9(0,0)
  rrect4% 2.4x3.1 on Top Paste: 9(0,0)
  rrect4% 2.4x3.1 on Top Solder: 9(0,0)
  silkscreen extent -3.22,-2.5 1.4,2.5, body extent -3,-2.45 3,2.45, height 1.57
ESD_Overlay_Small [mil]
  silkscreen extent -62,-48 64,61
FCC_disclaimer [mil]
Fiducial10-20 [mm]
  round 1 smd mask+0.5: 1(0,0)
  Top Layer keep-out circle w1.178: c0,0 r0.5
Keystone_1902C [mil] "Hex Standoff, 4-40 threaded, nylon"
  body extent -145,-126 146,126, height 501
"NY PMS 440 0025 PH" [mm] "4-40 nylon screw and mounting hole"
  round 8 hole 3.2: 1(0,0)
  body extent -3.3,-3.3 3.3,3.3, height 2.69
Pb-Free_Overlay_Small [mil]
  silkscreen extent -46,-46 46,46
Phoenix_1792876 [mm] "Terminal Block, 5mm, 3x1, R/A, TH"
  rrect50% 1.7x1.7 hole 1.2: 1(-5,0)
  round 1.7 hole 1.2: 2(0,0) 3(5,0)
  silkscreen extent -8.02,-4.95 7.5,5.55, body extent -7.5,-4.95 7.5,5.55, height 13.6
PhoenixContact_1715721 [mm] "Phoenix Contact 1715721 used on LM3445 design from Longmont"
  rrect5% 1.905x1.905 hole 1.3: 1(-2.54,0)
  round 1.9 hole 1.3: 2(2.54,0)
  silkscreen extent -5.82,-4.98 5.08,5.2, body extent -5.82,-4.6 5.08,5.2, height 14.2
PowerDI5 [mm] "Diodes Inc recommended land pattern, ap02001.pdf rev 60"
  rect 1.4x1.39 smd: 1(-1.991,0.92) 2(-1.991,-0.92)
  rect 4.86x3.36 smd: 3(1.991,0)
  silkscreen extent -1.7,-2.1 3.8,2.1, body extent -2.27,-2.03 4.33,2.03, height 1.17
RGW0020A [mm] "QFN, 20-Leads, Body 5x5mm, Pitch 0.65mm, Thermal Pad 3.15x3.15mm, TI Recommended"
  oval 0.75x0.3 smd: 1(-2.325,1.3) 2(-2.325,0.65) 3(-2.325,0) 4(-2.325,-0.65) 5(-2.325,-1.3) 11(2.325,-1.3) 12(2.325,-0.65) 13(2.325,0) 14(2.325,0.65) 15(2.325,1.3)
  oval 0.3x0.75 smd: 6(-1.3,-2.325) 7(-0.65,-2.325) 8(0,-2.325) 9(0.65,-2.325) 10(1.3,-2.325) 16(1.3,2.325) 17(0.65,2.325) 18(0,2.325) 19(-0.65,2.325) 20(-1.3,2.325)
  rect 3.15x3.15 smd paste-1.575: 21(0,0)
  silkscreen extent -2.73,-2.73 2.73,2.73, body extent -2.58,-2.57 2.57,2.58, height 1.01
RNP0030A [mm] "QFN, 30-Leads, Body 6x4mm, Pitch 0.5mm, Thermal Pad 4.6x2.2mm"
  rrect40% 0.75x0.25 smd: 1(-1.825,2.5) 2(-1.825,2) 3(-1.825,1.5) 4(-1.825,1) 5(-1.825,0.5) 6(-1.825,0) 7(-1.825,-0.5) 8(-1.825,-1) 9(-1.825,-1.5) 10(-1.825,-2) 11(-1.825,-2.5) 16(1.825,-2.5) 17(1.825,-2) 18(1.825,-1.5) 19(1.825,-1) 20(1.825,-0.5) 21(1.825,0) 22(1.825,0.5) 23(1.825,1) 24(1.825,1.5) 25(1.825,2) 26(1.825,2.5)
  rrect40% 0.25x0.6 smd: 12(-0.75,-2.9) 13(-0.25,-2.9) 14(0.25,-2.9) 15(0.75,-2.9) 27(0.75,2.9) 28(0.25,2.9) 29(-0.25,2.9) 30(-0.75,2.9)
  rrect5% 2.2x4.6 smd paste-3: 31(0,0)
  rrect10% 0.98x0.96 on Top Paste: 31A(-0.59,1.74) 31A(-0.59,0.58) 31A(-0.59,-0.58) 31A(-0.59,-1.74) 31A(0.59,1.74) 31A(0.59,0.58) 31A(0.59,-0.58) 31A(0.59,-1.74)
  silkscreen extent -2.17,-3.18 2.17,3.18, body extent -2.07,-3.07 2.07,3.07, height 0.81
SMA [mm] "Molded Diode, 2-Leads, Body 4.3x2.6mm, IPC Medium Density, based on OnSemi component dimensions and land pattern"
  rect 2x2 smd: 1(-2,0) 2(2,0)
  silkscreen extent -3.66,-1.57 2.79,1.57, body extent -2.6,-1.3 2.6,1.3, height 2.42
SMB [mil] "Molded Diode, 2-Leads, Body 5.4x3.6mm, IPC Medium Density, based on OnSemi component dimensions"
  rect 85x107.99 smd: 1(-87.01,0) 2(87.01,0)
  silkscreen extent -155,-82 125,82, body extent -106,-71 106,71, height 91
SOD-123 [mm] "On Semi recommended land pattern"
  rect 0.915x1.22 smd: 1(-1.637,0) 2(1.637,0)
  silkscreen extent -2.74,-1.17 2.03,1.17, body extent -1.93,-0.9 1.93,0.9, height 1.35
SOT-23 [mm] "SOT23, 3-Leads, Body 2.9x1.3mm, Pitch 0.95mm, Lead Span 2.5mm, IPC Medium Density"
  rrect50% 1x0.6 smd: 1(-1.2,0.95) 2(-1.2,-0.95) 3(1.2,0)
  silkscreen extent -1.63,-1.5 0.7,1.5, body extent -1.16,-1.45 1.21,1.45, height 1
TI_Stacked_Overlay_Small [mil]
  silkscreen extent -418,-98 418,98
TSW-104-07-G-S [mm] "Samtec 100mil, 1x4, 230 mil above insulator"
  rrect6% 1.65x1.65 hole 1.016: 1(-3.81,0)
  round 1.65 hole 1.016: 2(-1.27,0) 3(1.27,0) 4(3.81,0)
  silkscreen extent -5.16,-1.27 5.08,1.65, body extent -5.08,-1.27 5.08,1.27, height 8.38
WE-HCA1 [mm] "Wurth Electronik recommended land pattern"
  rect 4.5x5 smd: 1(-5.25,0) 2(5.25,0)
  silkscreen extent -7.35,-6.85 7.35,6.85, body extent -7.1,-6.68 7.12,6.64, height 6.5
XAL7030 [mm] "Coilcraft XAL7030 7.5 x.7.5 x 3.1 mm"
  rect 1.78x6.55 smd: 1(-2.36,0) 2(2.36,0)
  silkscreen extent -4,-4 4,4, body extent -4,-4 4,4, height 3.1
ZL_1000x2000 [mm] "Capacitor, Electrolytic, Radial; Body 10 x 20 mm (Dia.xH typ); Pin Spacing 5 mm (typ)"
  rect 1.5x1.5 hole 0.9: 1(-2.5,0)
  round 1.5 hole 0.9: 2(2.5,0)
  silkscreen extent -5.3,-5.3 5.3,5.3, body extent -5.21,-5.24 5.24,5.24, height 22.01

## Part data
C1: "CAP, CERM, 0.47 µF, 25 V, +/- 10%, X5R, 0603"
C2 C26: "CAP, AL, 470 µF, 35 V, +/- 20%, TH"
C3: "CAP, CERM, 2.2 µF, 35 V, +/- 10%, X5R, 0603"
C4 C5 C19 C21: "CAP, CERM, 10 µF, 50 V, +/- 10%, X7R, 1210"
C6 C7: "CAP, CERM, 0.47 µF, 50 V, +/- 10%, X7R, 0805"
C8 C9 C10 C33: "CAP, CERM, 22 µF, 25 V, +/- 10%, X7R, 1210"
C11 C38 C46 C48 C53 C59 C60 C61: "CAP, CERM, 1 µF, 50 V, +/- 10%, X5R, 0603"
C12 C14 C15 C22 C25 C27 C36 C42 C44 C52 C54 C55: "CAP, CERM, 0.1 µF, 50 V, +/- 10%, X7R, 0603"
C13: "CAP, CERM, 4.7 pF, 50 V, +/- 5%, C0G/NP0, 0805"
C16: "CAP, CERM, 0.022 µF, 50 V, +/- 10%, X7R, 0805"
C17 C18 C20 C64: "CAP, CERM, 10 µF, 50 V,+/- 10%, X5R, 1206"
C23 C24: "CAP, CERM, 4.7 µF, 50 V, +/- 10%, X7R, 1210"
C29 C30 C63: "CAP, CERM, 1 µF, 25 V, +/- 10%, X7R, 0805"
C31 C35 C41 C50 C57 C62: "CAP, CERM, 47 µF, 25 V, +/- 20%, X5R, 1206_190"
C32: "CAP, CERM, 0.027 µF, 25 V, +/- 10%, X7R, 0603"
C34 C37 C39 C40 C43 C45 C47 C49 C51 C56 C58: "CAP, CERM, 10 µF, 35 V, +/- 10%, X5R, 0805"
C65: "CAP, CERM, 22 pF, 50 V,+/- 5%, C0G/NP0, 0603"
D1 D3 D4: "Diode, Zener, 3.3 V, 550 mW, SMB"
D2: library part PDS560-13, "Diode, Schottky, 60 V, 7 A, PowerDI5"
D5 D6 D7 D8: "Diode, Schottky, 60 V, 2 A, SMA"
D9: "Diode, Switching, 100 V, 0.15 A, SOD-123"
FID1 FID2 FID3: "Fiducial mark.  There is nothing to buy or mount."
H1 H2 H5 H6: "Machine Screw, Round, #4-40 x 1/4, Nylon, Philips panhead"
H7 H8 H13 H14: "Standoff, Hex, 0.5\"L #4-40 Nylon"
J1: "Header, 100mil, 4x1, Gold, TH"
J2 J3: "Terminal Block, 5mm, 3x1, R/A, TH"
J4: "Terminal Block, 5.08 mm, 2x1, TH"
J5 J6 J7 J8: "SMA Straight Jack, Gold, 50 Ohm, TH"
L1: "Inductor, Shielded, Composite, 10 µH, 5.3 A, 0.057 ohm, SMD"
L2: "Inductor, Shielded Drum Core, WE-Perm, 33uH, 5.5A, 0.0305 ohm, SMD"
L3 L4: "Inductor, Shielded, Composite, 2.2uH, 12.9A, 0.0137 ohm, SMD"
Logo1: library part ESD_Susceptible, "ESD Susceptible Symbol"
Logo2: library part Pb-Free
Logo3: library part FCC_disclaimer, "FCC_disclaimer"
Logo4: library part TI_Logo, "Texas Instrument Corporate Signature"
Q1 Q3: library part "BC847CLT1G, ON Semiconductor", "Transistor, NPN, 45 V, 0.1 A, SOT-23"
Q2: "MOSFET, N-CH, 100 V, 0.17 A, SOT-23"
Q4 Q5 Q6: library part "BC857C-7-F, Diodes Inc.", "Transistor, PNP, 45 V, 0.1 A, SOT-23"
R1: "RES, 240 k, 5%, 0.125 W, 0805"
R2 R31 R59 R60 R61 R62 R63: "RES, 0, 5%, 0.1 W, 0603"
R3 R67 R68: "RES, 47 k, 5%, 0.125 W, 0805"
R4: "RES, 68 k, 5%, 0.1 W, 0603"
R5: "RES, 470, 5%, 0.1 W, 0603"
R6 R65: "RES, 100, 1%, 0.1 W, 0603"
R7: "RES, 1.00 M, 1%, 0.1 W, 0603"
R8 R10 R14: "RES, 4.70 k, 1%, 0.1 W, 0603"
R9: "RES, 20 k, 5%, 0.1 W, 0603"
R11 R33 R36 R37 R39 R42 R47 R48 R51 R54 R57: "RES, 10.0 k, 1%, 0.1 W, 0603"
R12 R49 R66: "RES, 1.00 k, 1%, 0.1 W, 0603"
R13: "RES, 2.0 k, 5%, 0.125 W, 0805"
R15 R16 R28: "RES, 3.3 k, 5%, 0.1 W, 0603"
R17 R20: "TRIMMER 10K OHM 0.1W"
R18: "RES, 180 k, 5%, 0.1 W, 0603"
R19: "RES, 33 k, 5%, 0.1 W, 0603"
R21: "RES, 2.2 k, 5%, 0.1 W, 0603"
R22: "RES, 3.6 k, 5%, 0.1 W, 0603"
R23 R26 R32 R35 R38 R41 R44 R45 R46 R55: "RES, 100 k, 1%, 0.1 W, 0603"
R24 R56: "RES, 22 k, 5%, 0.1 W, 0603"
R25: "RES, 59.0 k, 1%, 0.1 W, 0603"
R27: "RES, 442 k, 1%, 0.1 W, 0603"
R29: "RES, 470, 5%, 0.125 W, 0805"
R30: "RES, 220, 5%, 0.1 W, 0603"
R34 R40: "RES, 330, 5%, 0.1 W, 0603"
R43 R52: "RES, 1.2 M, 5%, 0.1 W, 0603"
R50 R53: "RES, 120 k, 5%, 0.1 W, 0603"
R58: "RES, 93.1 k, 1%, 0.1 W, 0603"
R64: "RES, 10, 5%, 0.1 W, 0603"
U1: "3.5V to 36V 5A Synchronous Step-Down Voltage Regulator, RNP0030A (WQFN-30)"
U2 U7 U9: "36V, Low Power, RRO, General Purpose Operational Amplifier, D0008A (SOIC-8)"
U3: "Adjustable Precision Shunt Regulator, 34 ppm / degC, 100 mA, 0 to 70 degC, 3-pin SOT-23 (DBZ), Green (RoHS & no Sb/Br)"
U4: "40V, 5A SIMPLE SWITCHER, 2.2MHz Step-Down Regulator with 40uA IQ, DDA0008E (SOIC-8)"
U5 U6: "36-V, 1-A, 4.17-uVRMS, RF LDO Voltage Regulator, RGW0020A (VQFN-20)"
U8 U10: "Single Output High PSRR LDO, 1 A, Adjustable -1.18 to -33 V Output, -3 to -36 V Input, with Ultra-Low Noise, 20-pin VQFN (RGW), -40 to 125 degC, Green (RoHS & no Sb/Br)"
ZZ1 ZZ2 ZZ3: library part AssemblyNote
ZZ4: library part AssemblyNoteLabel

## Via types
v1: diameter 30, hole 15, Top Layer to Bottom Layer, tented both sides, 424 vias
v2: diameter 19.68, hole 7.87, Top Layer to Bottom Layer, 39 vias

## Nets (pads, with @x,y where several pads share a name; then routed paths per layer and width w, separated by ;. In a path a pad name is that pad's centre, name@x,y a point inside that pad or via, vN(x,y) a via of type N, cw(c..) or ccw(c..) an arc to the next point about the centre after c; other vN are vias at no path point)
16V: C14.1 C44.1 C52.1 Q3.2 R17.3 R18.2 R20.1 U2.8 U7.8 U9.8 | length 491.9
  Top Layer w15: R20.1@2054.13,1989.62 v1(2102.63,1989.62) ; R17.3@2054.13,2081.88 v1(2102.63,2081.88) ; v1(2137.5,3513.75) C44.1@2137.5,3467.25 2137.5,3417.53 2151.73,3403.3 U7.8@2173.13,3403.3 ; v1(2197,1800.25) 2199,1798.25 U9.8@2199,1673.25
  Top Layer w20: U2.8@1632.72,2918.25 1646.85,2918.25 1665.5,2899.6 C14.1@1665.5,2856.25 v1(1665.5,2810.76)
24VIN: C19.1 J4.2 L3.1 L4.1 Q3.3 R14.2 | length 254.8
  Top Layer w20: v1(1781,2265.25) C19.1@1836.91,2265.25 1836.91,2162.83 R14.2@1837,2162.75 1837.75,2163.5 Q3.3@1933,2163.5
  other v1: 1781,2185.25 1781,2225.25 188,2387.25 228,2387.25 188,2427.25 228,2427.25 188,2467.25 228,2467.25 244,2813.25 284,2813.25 244,2853.25 284,2853.25 244,2893.25 284,2893.25 244,2933.25 284,2933.25
+3.3V: C20.1 D1.1 R12.1 R13.1 R15.2 R16.2 | length 1080.8
  Top Layer w20: R15.2@1218.5,3278.25 v1(1265,3278.25) ; v1(1338,3274.25) D1.1@1338,3343.24
  Top Layer w25: v1(1481,3305.57) C20.1@1481,3355.07
  Top Layer w35: R16.2@1976.5,2785.25 v1(2026,2785.25)
  Bottom Layer w35: 1453,3345.25 1570.75,3345.25 2026,2890 v1(2026,2785.25)
+VO: C7.2 C8.1 C9.1 C10.1 C13.2 C37.2 C43.2 C45.2 J5.1 L1.2 R2.1 R7.1 R38.2 U5.13 U5.15 U5.16 U6.13 U6.15 U6.16 | length 2566.2
  Top Layer w10: v1(3162,2389) 3187.21,2363.79 U5.13@3207.96,2363.79 ; v1(3162,3197) 3187.21,3171.79 U6.13@3207.96,3171.79 ; C37.2@3234,2203 3248.31,2217.32 U5.16@3248.31,2272.25 ; C43.2@3234,3007 3248.31,3021.32 U6.16@3248.31,3080.25
  Top Layer w20: v1(1745.85,3415.1) C45.2@1745.85,3355.3 1749.81,3359.25 R38.2@1818.5,3359.25 1818.5,3612 1946.66,3740.16 J5.1@3346.46,3740.16
  Top Layer w25: R2.1@1413.5,2811.65 1413.6,2811.76 R7.1@1479,2811.76 1496.5,2794.25 C13.2@1555,2794.25 ; C7.2@1768,2564.25 v1(1768,2621.25) ; C10.1@2149,2591.34 C10.1@2157,2583.34 ; v1(3172,2203) C37.2@3229,2203 ; v1(3172,3007) C43.2@3229,3007
  other v1: 1886,2637.25 1936,2637.25 1986,2637.25 2036,2637.25
-3.3V: C33.1 C55.1 D4.2 R29.1 U9.4 | length 106.2
  Top Layer w15: U9.4@1984.43,1523.25 2019.15,1523.25 2037.22,1505.18 C55.1@2037.22,1459.25
-VO: C29.2 C30.2 C31.2 C51.2 C58.2 C62.2 C63.2 C64.2 D2.1 D2.2 J7.1 R29.2 R31.1 R44.2 R66.1 U4.7 U4.9@1132.72,863 U8.13 U8.15 U8.16 U10.13 U10.15 U10.16 | length 554.7
  Top Layer w10: v1(3162,815.46) 3187.21,790.25 U8.13@3207.96,790.25 ; v1(3162,1604.46) 3187.21,1579.25 U10.13@3207.96,1579.25 ; C58.2@3234,1415.25 3248.31,1429.57 U10.16@3248.31,1487.72
  Top Layer w20: v1(1502,888) 1502,840.5 R31.1@1504.5,838 ; v1(1858,1364) R29.2@1914,1364 ; v1(1914.72,1435.84) R44.2@1914.72,1485.76 ; R66.1@2472.5,1596 v1(2472.5,1640.5) ; C64.2@2567,1595.93 v1(2567,1644)
  Top Layer w25: v1(3172,626) C51.2@3229,626 ; v1(3172,1415.25) C58.2@3229,1415.25
  other v1: 1272,269 1332,269 1392,269 1452,269 1512,269 1572,269 1632,269 1692,269 1752,269 1812,269 1872,269 1932,269 1992,269 2052,269 2112,269 2172,269 2232,269 2292,269 2352,269 2412,269 2472,269 1272,329 1332,329 1392,329 1452,329 1512,329 1572,329 1632,329 1692,329 1752,329 1812,329 1872,329 1932,329 1992,329 2052,329 2112,329 2172,329 2232,329 2292,329 2352,329 2412,329 2472,329 2532,329 1272,389 1332,389 1392,389 1452,389 1512,389 1572,389 1632,389 1692,389 1752,389 1812,389 1872,389 1932,389 1992,389 2052,389 2112,389 2172,389 2232,389 2292,389 2352,389 2412,389 2472,389 2532,389 2592,389 1272,449 1332,449 1392,449 1452,449 1512,449 1572,449 1632,449 1692,449 1752,449 1812,449 1872,449 1932,449 1992,449 2052,449 2112,449 2172,449 2232,449 2292,449 2352,449 2412,449 2472,449 2532,449 2592,449 2652,449 1272,509 1332,509 1392,509 1452,509 1512,509 1572,509 1632,509 1692,509 1752,509 1812,509 1872,509 1932,509 1992,509 2052,509 2112,509 2172,509 2232,509 2292,509 2352,509 2412,509 2472,509 2532,509 2592,509 2652,509 2712,509 1272,569 1332,569 1392,569 1452,569 1512,569 1572,569 1632,569 1692,569 1752,569 1812,569 1872,569 1932,569 1992,569 2052,569 2112,569 2172,569 2232,569 2292,569 2352,569 2412,569 2472,569 2532,569 2592,569 2652,569 2712,569 2772,569 1111,581 1812,629 1872,629 1932,629 1992,629 2052,629 2112,629 2172,629 2232,629 2292,629 2352,629 2412,629 2472,629 2532,629 2592,629 2652,629 2712,629 2772,629 2832,629 1111,631 1161,631 1111,681 1161,681 1812,689 1872,689 1932,689 1992,689 2052,689 2112,689 2172,689 2232,689 2292,689 2352,689 2412,689 2472,689 2532,689 2592,689 2652,689 2712,689 2772,689 2832,689 2892,689 1111,731 1161,731 1812,749 1872,749 1932,749 1992,749 2052,749 2112,749 2172,749 2232,749 2292,749 2352,749 2412,749 2472,749 2532,749 2592,749 2652,749 2712,749 2772,749 2832,749 2892,749 1812,809 1872,809 1932,809 1992,809 2052,809 2112,809 2172,809 2232,809 2292,809 2352,809 2412,809 2472,809 2532,809 2592,809 2652,809 2712,809 2772,809 2832,809 2892,809 1090,1100 1040,1150 1090,1150 1040,1200 1090,1200 1040,1250 1090,1250
  other v2: 1111.06,786.23 1154.37,786.23 1111.06,837.41 1154.37,837.41 1111.06,888.59 1154.37,888.59 1111.06,939.77 1154.37,939.77
A: R20.2 R50.2 | length 527.9
  Top Layer w15: R50.2@1785.68,1743.23 1823.45,1781 2091,1781 2182.09,1872.09 R20.2@2182.09,1950.25
AGND: C19.2 C20.2 C44.2 C45.1 C48.1 C52.2 C54.1 C55.2 D1.2 J4.1 J5.2 J5.3 J5.4 J5.5 J6.2 J6.3 J6.4 J6.5 J7.2 J7.3 J7.4 J7.5 J8.2 J8.3 J8.4 J8.5 R19.1 R42.1 R54.1 R59.2 R60.2 R61.2 R62.2 R63.2 R65.2 R67.2 R68.1 U3.3 U7.4 U9.3 | length 1654.2
  Top Layer w15: v1(1675,1874.51) U3.3@1675,1923.01 ; v1(1848.21,1565.27) C54.1@1848.21,1615.25 ; U9.3@1984.43,1573.25 2050.15,1573.25 2100.21,1523.19 C55.2@2100.21,1459.25 v1(2100.21,1410.19) ; v1(2089,1745) 2131.45,1745 C52.2@2136.68,1750.23
  Top Layer w20: v1(1769,3230.25) 1769.93,3231.19 R42.1@1818.55,3231.19 ; U7.4@1958.57,3253.3 1986.96,3253.3 v1(2008,3232.25) ; v1(2072.5,3573.76) C48.1@2072.5,3531.25 2074.5,3529.24 C44.2@2074.5,3467.25 ; v1(2338.72,1417.77) R54.1@2338.72,1463.76
  Top Layer w25: v1(73,1925.25) 74.5,1926.75 R62.2@113,1926.75 113,1957.85 103.6,1967.25 v1(93,1967.25) ; v1(124,1997.25) R60.2@175.5,1997.25 175.5,1954.76 v1(175,1954.25) ; v1(186,3436.25) R61.2@233.5,3436.25 233.5,3386.76 v1(233,3386.25) ; R59.2@671,3211.75 v1(671,3257.25) ; v1(711,3273.25) R63.2@755.5,3273.25 755.5,3230.75 v1(756,3230.25) ; v1(1277.01,3517.26) D1.2@1353,3517.26 v1(1353,3593.25) ; C20.2@1481,3488.93 v1(1481,3538.43) ; R65.2@1505.5,741 v1(1547,741) ; C45.1@1665.85,3355.3 v1(1665.85,3404.8) ; v1(1918,1831) R68.1@1973,1831 1979.5,1837.5 R19.1@1979.5,1912.25 ; C19.2@1951.09,2265.25 1951.83,2266 R67.2@2035,2266 v1(2035,2208)
AGND1: C14.2 C16.1 C17.2 C18.2 C22.2 R11.1 R63.1 U1.19 U2.4 | length 474.3
  Top Layer w9: v1(1022,2789.25) 1022,2783.99 1025.37,2780.62 U1.19@1074.15,2780.62
  Top Layer w20: R63.1@818.5,3273.25 864,3273.25 v1(865,3272.25) ; v1(1269,3107) C17.2@1315.07,3107 ; v1(1506.5,3027.5) R11.1@1506.5,3066 ; U2.4@1847.28,3068.25 1905.5,3068.25 C22.2@1924,3086.75 v1(1924,3133.25)
  Top Layer w25: C16.1@1406,3196 v1(1455.5,3196) ; C18.2@1518,3254.93 1535,3271.93 v1(1535,3303) ; C14.2@1728.5,2856.25 v1(1777,2856.25)
B: R17.2 R41.2 | length 1672.5
  Top Layer w15: v1(1768,3295.25) R41.2@1818.5,3295.25 ; R17.2@2182.09,2121.25 2186.34,2117 v1(2334,2117)
  Bottom Layer w15: v1(1768,3295.25) 1863,3295.25 2334,2824.25 v1(2334,2117)
FB: R27.1 R56.2 U4.5 | length 1745.8
  Top Layer w15: R56.2@2467.72,1526.75 2469.22,1528.25 v1(2518,1528.25)
  Top Layer w20: U4.5@1240,788 1240,761 1260,741 R27.1@1311.5,741 v1(1311.5,780.5)
  Bottom Layer w20: v1(1311.5,780.5) 1462,931 1976,931 2518,1473 v1(2518,1528.25)
NetC1_1: C1.1 L1.1 U1.1 U1.2 U1.3 U1.4 U1.5
NetC1_2: C1.2 U1.6 | length 79.5
  Top Layer w9: U1.6@1217.85,2741.25 1258.5,2741.25
  Top Layer w10: 1258.5,2741.25 C1.2@1286,2713.75
NetC2_1: C2.1 C4.2 C5.2 C6.2 L3.2 R1.2 R5.2 R13.2 U1.20 U1.21 U1.22 | length 177.5
  Top Layer w20: v1(729.59,3046.25) R5.2@779.5,3046.25 ; C6.2@872,2700.25 v1(872,2756.25) ; v1(1154,3413.25) 1154,3343.76 R13.2@1155.5,3342.25
  other v1: 628,2770.25 668,2770.25 708,2770.25 748,2770.25
NetC3_2: C3.2 U1.7 | length 137.9
  Top Layer w9: U1.7@1217.85,2760.94 1337.82,2760.94 C3.2@1350.5,2748.25
NetC11_2: C11.2 R2.2 U1.8 | length 208.9
  Top Layer w9: U1.8@1217.85,2780.62 1319.47,2780.62 R2.2@1350.5,2811.65 C11.2@1350.5,2875.05
NetC12_1: C12.1 R1.1 R3.2 U1.18 | length 343.9
  Top Layer w9: R1.1@965,2801.25 984,2820.25 1030.38,2820.25 1050.33,2800.31 U1.18@1074.15,2800.31
  Top Layer w15: C12.1@842.5,2919.25 842.5,2843.75 841,2842.25 R3.2@856,2842.25 897,2801.25 R1.1@965,2801.25
NetC13_1: C13.1 R4.2 R7.2 U1.11 | length 647
  Top Layer w9: U1.11@1217.85,2839.68 1230.96,2839.68 1279,2887.72 1279,3008.25 v1(1304,3033.25) ; v1(1479,2921.25) R7.2@1479,2874.75 1554.5,2874.75 C13.1@1555,2874.25
  Top Layer w15: v1(1304,3033.25) R4.2@1349.5,3033.25
  Bottom Layer w15: v1(1304,3033.25) 1402,3033.25 1479,2956.25 v1(1479,2921.25)
NetC15_1: C15.1 Q1.3 R5.1 | length 291
  Top Layer w15: R5.1@842.5,3046.25 C15.1@842.5,2982.25 845.5,2985.25 Q1.3@1068.24,2985.25
NetC16_2: C16.2 U1.10 | length 492.1
  Top Layer w9: U1.10@1217.85,2819.99 1248.74,2819.99 1267,2838.25 v1(1268,2838.25)
  Top Layer w15: v1(1262,3168) 1298,3168 C16.2@1326,3196
  Bottom Layer w15: v1(1262,3168) 1230,3136 1230,2963.96 1246.2,2947.76 1246.2,2860.05 v1(1268,2838.25)
NetC17_1: C17.1 R4.1 R8.2 | length 181.9
  Top Layer w15: R4.1@1413.5,3031.85 R4.1@1413.5,3032.25 ; C17.1@1448.93,3107 1413.5,3071.57 R4.1@1413.5,3032.25 ; R8.2@1479.5,2969.25 1476.5,2969.25 R4.1@1413.5,3032.25
NetC18_1: C18.1 R9.2 R11.2 U2.5 | length 224.6
  Top Layer w15: C18.1@1538.99,3131.76 C18.1@1540.5,3130.25 ; R9.2@1596,3130.5 1586.57,3121.07 C18.1@1518,3121.07 1569.5,3069.57 R11.2@1569.5,3066 1571.75,3068.25 U2.5@1632.72,3068.25
NetC21_1: C21.1 Q3.1 R14.1 U3.1 | length 268.5
  Top Layer w15: U3.1@1712.4,2017.5 1806.16,2017.5 C21.1@1814,2025.34 1837,2048.34 R14.1@1837,2099.76 1879.2,2099.76 1895.6,2083.36 Q3.1@1895.6,2069.01
NetC21_2: C21.2 R18.1 R19.2 U3.2 | length 388.4
  Top Layer w15: U3.2@1637.6,2017.5 1683.84,1971.25 1723,1971.25 1783.09,1911.17 C21.2@1814,1911.17 1815.09,1912.25 R19.2@1916.5,1912.25 R18.1@1916.5,1977.25
NetC22_1: C22.1 R21.1 U2.3 | length 144
  Top Layer w15: U2.3@1847.28,3018.25 1918.5,3018.25 C22.1@1924,3023.76 R21.1@1989,3023.76
NetC23_1: C23.1 C24.1 C25.1 C26.1 C63.1 L4.2 Q6.2 R22.2 U4.2
NetC27_1: C27.1 R64.2 | length 68
  Top Layer w20: R64.2@1374.5,938 C27.1@1442.5,938
NetC27_2: C27.2 U4.1 | length 672.7
  Top Layer w20: v1(968,982) 968,954 984,938 U4.1@1025.43,938 ; v1(1505,981) 1505,938.5 C27.2@1505.5,938
  Bottom Layer w20: v1(968,982) 969,981 v1(1505,981)
NetC32_1: C32.1 U4.6 | length 71.5
  Top Layer w20: U4.6@1240,838 C32.1@1311.5,838
NetC32_2: C32.2 D3.2 R25.1 R26.2 R28.1 R31.2 | length 977
  Top Layer w20: D3.2@758,409.99 826.02,478.01 R26.2@877,478.01 960.5,478.01 961,478.5 v1(1009.5,478.5) 1025,494 R25.1@1025,560.5 ; v1(1374.5,790.5) C32.2@1374.5,838 R31.2@1441.5,838
  Bottom Layer w20: v1(1009.5,478.5) 1062.5,478.5 v1(1374.5,790.5)
NetC34_2: C34.2 C35.1 C36.1 D5.2 R32.1 U5.1 U5.20
NetC38_2: C38.2 U5.14 | length 54.5
  Top Layer w9: C38.2@3153.5,2338 3153.69,2338.2 U5.14@3207.96,2338.2
NetC39_2: C39.2 R33.2 R34.2 | length 155.7
  Top Layer w15: R34.2@3385.5,2599 3386,2598.5 C39.2@3386,2521 ; C39.2@3390,2521 3438.54,2521 R33.2@3459,2500.54
NetC40_2: C40.2 C41.1 C42.1 D6.2 J6.1 R35.1 U6.1 U6.20 | length 693.4
  Top Layer w15: D6.2@3798.31,3104.25 3937.01,3242.95 J6.1@3937.01,3740.16
NetC46_2: C46.2 U6.14 | length 54.7
  Top Layer w9: C46.2@3153.5,3146.79 3154.09,3146.2 U6.14@3207.96,3146.2
NetC47_2: C47.2 R37.2 R40.2 | length 155.8
  Top Layer w15: R40.2@3390.5,3409 3390,3408.5 C47.2@3390,3332.25 3435.28,3332.25 R37.2@3459,3308.54
NetC48_2: C48.2 R39.1 U7.5 | length 389.9
  Top Layer w15: C48.2@2009.5,3531.25 2009.5,3467.45 R39.1@2009.35,3467.3 2009.35,3341.91 2097.96,3253.3 U7.5@2173.13,3253.3
NetC49_2: C49.2 C50.1 D7.1 J8.1 R43.2 U8.1 U8.20 | length 590.8
  Top Layer w15: D7.1@3820.26,739.25 3937.01,622.5 J8.1@3937.01,196.85
NetC53_2: C53.2 R46.2 R47.1 | length 142
  Top Layer w15: C53.2@3388.5,944 R46.2@3459,944 R47.1@3530.5,944
NetC54_2: C54.2 R48.2 R53.1 | length 711.7
  Top Layer w15: v1(1785.22,1565.22) C54.2@1785.22,1615.25 R48.2@1785.22,1678.25 ; v1(2273.72,1415.54) R53.1@2273.72,1463.76
  Bottom Layer w15: v1(1785.22,1565.22) 1856.44,1494 2195.25,1494 v1(2273.72,1415.54)
NetC56_2: C56.2 C57.1 D8.1 R52.2 U10.1 U10.20
NetC59_2: C59.2 R55.2 R57.1 | length 142.2
  Top Layer w15: C59.2@3388.5,1731.25 3458.75,1731.25 R55.2@3459,1731 3530.32,1731 R57.1@3530.5,1731.18
NetC60_2: C60.2 U8.14 | length 74.6
  Top Layer w9: C60.2@3133.5,764.25 C60.2@3143.5,764.25 3207.55,764.25 U8.14@3207.96,764.66
NetC61_2: C61.2 U10.14 | length 54.7
  Top Layer w10: C61.2@3153.5,1554.25 3207.37,1554.25 U10.14@3207.96,1553.66
NetC64_1: C64.1 R49.2 R56.1 | length 177.3
  Top Layer w20: R49.2@2394,1455.04 R49.2@2402.72,1463.76 R56.1@2467.72,1463.76 2565.32,1463.76 C64.1@2567,1462.07
NetC65_1: C65.1 Q1.1 Q2.1 R10.2 R30.2 | length 273.4
  Top Layer w15: R30.2@913,3248.5 913.5,3248.01 C65.1@913.5,3185 914.5,3184 R10.2@914.5,3119.25 953.1,3119.25 973.6,3098.76 Q2.1@973.6,3084.01 Q1.1@973.6,3022.81
NetD2_3: D2.3 L2.1 R64.1 U4.8
NetD3_1: D3.1 R24.2 R26.1 U4.3 | length 572.3
  Top Layer w20: R26.1@877,541 823,541 779.99,584.01 D3.1@758,584.01 757.5,584.51 R24.2@757.5,690 905.5,838 U4.3@1025.43,838
NetD5_1: D5.1 J2.1
NetD6_1: D6.1 J2.3
NetD7_2: D7.2 J3.1
NetD8_2: D8.2 J3.3
NetD9_1: D9.1 R25.2 U4.4 | length 164.7
  Top Layer w15: R25.2@1025,623.5 1025,704.53 D9.1@1025.47,705 1025.47,787.96 U4.4@1025.43,788
NetD9_2: D9.2 Q4.3 R28.2 | length 3840
  Top Layer w15: v1(1048,3327.25) Q4.3@1048,3372.5
  Top Layer w25: v1(847,705) D9.2@896.53,705 941,660.53 R28.2@941,541.5
  Bottom Layer w15: v1(847,705) 812,670 651,670 454,867 454,2190.25 275,2369.25 275,2720.25 441,2886.25 441,3095.25 534,3188.25 909,3188.25 v1(1048,3327.25)
NetJ1_1: J1.1 R9.1 | length 1024.4
  Top Layer w15: J1.1@1003,3763.25 1382,3763.25 1594.3,3550.95 1594.3,3207.5 R9.1@1596,3207.5
NetJ1_2: J1.2 R21.2 | length 1663.6
  Top Layer w15: J1.2@903,3763.25 903,3808.25 926,3831.25 1366,3831.25 1617,3580.25 1617,3260.25 1701,3176.25 1946,3176.25 1989,3133.25 R21.2@1989,3086.75
NetQ1_2: Q1.2 R6.2 U1.17 | length 198.4
  Top Layer w9: Q1.2@973.76,2947.85 973.76,2926.5 995.5,2904.76 R6.2@995.5,2879.25 1025,2879.25 1038,2866.25 1038,2836.25 1054.26,2819.99 U1.17@1074.15,2819.99
NetQ2_3: Q2.3 Q4.1 R12.2 | length 259.8
  Top Layer w15: Q4.1@1010.6,3278.01 1010.6,3178.9 Q2.3@1011,3178.5 1117.75,3178.5 R12.2@1155.5,3216.25
NetQ4_2: Q4.2 R15.1 | length 70.2
  Top Layer w15: Q4.2@1085.4,3278.01 1155.26,3278.01 R15.1@1155.5,3278.25
NetQ5_1: Q5.1 U2.1 | length 67.5
  Top Layer w15: U2.1@1847.28,2918.25 1911.35,2918.25 Q5.1@1913.76,2920.65
NetQ5_2: Q5.2 R16.1 U2.2 | length 305.8
  Top Layer w15: U2.2@1847.28,2968.25 1816,2968.25 1795,2947.25 1795,2899.25 1848.4,2845.85 Q5.2@1913.76,2845.85 1913.76,2790.99 R16.1@1914.5,2790.25
NetQ5_3: Q5.3 R49.1 R66.2 | length 1610.1
  Top Layer w15: v1(1948,2882.25) 1949,2883.25 Q5.3@2008.24,2883.25 ; R49.1@2402.72,1526.75 2409.5,1533.54 R66.2@2409.5,1596 v1(2409.5,1644.5)
  Bottom Layer w15: v1(1948,2882.25) 1948,2803.25 2267,2484.25 2267,1787.01 v1(2409.5,1644.5)
NetQ6_1: Q6.1 R22.1 R23.2 | length 131.1
  Top Layer w15: R23.2@513.5,1549 504.5,1539.99 R22.1@504.5,1487 525.4,1466.09 Q6.1@525.4,1430.24
NetQ6_3: Q6.3 R24.1 | length 731.3
  Top Layer w15: Q6.3@488,1335.76 488,1327 v1(517,1298) ; R24.1@694.5,690 v1(694.5,739.5)
  Bottom Layer w15: v1(517,1298) 517,917.01 v1(694.5,739.5)
NetR8_1: R8.1 U2.6 U2.7 | length 202.7
  Top Layer w15: R8.1@1542.5,2969.25 1543.5,2968.25 U2.7@1632.72,2968.25 1655.83,2968.25 1672,2984.42 1672,3006.25 1660,3018.25 U2.6@1632.72,3018.25
NetR17_1: R17.1 R67.1 | length 130.6
  Top Layer w15: R17.1@2054.13,2160.62 2115,2221.49 R67.1@2115,2266
NetR20_3: R20.3 R68.2 | length 80.4
  Top Layer w15: R68.2@2053,1831 2053,1909.75 R20.3@2054.13,1910.88
NetR27_2: R27.2 R65.1 | length 68
  Top Layer w20: R27.2@1374.5,741 R65.1@1442.5,741
NetR32_2: R32.2 R33.1 U5.3 | length 140.1
  Top Layer w9: U5.3@3391.03,2363.79 R32.2@3456.21,2363.79
  Top Layer w15: R32.2@3456.21,2363.79 3459,2366.57 R33.1@3459,2437.54
NetR34_1: R34.1 R40.1 U7.6 U7.7 | length 2749.1
  Top Layer w15: R34.1@3322.5,2599 2936,2599 2231.7,3303.3 U7.6@2173.13,3303.3 2136.96,3303.3 2127,3313.25 2127,3343.25 2137.04,3353.3 U7.7@2173.13,3353.3 2270.3,3353.3 2326,3409 R40.1@3327.5,3409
